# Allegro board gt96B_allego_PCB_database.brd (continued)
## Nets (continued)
GND: BT1.3(N) C1.2(B<0>) C2.2(B<0>) C3.2(B<0>) C4.2(B<0>) C5.2(B<0>) C6.2(B<0>) C7.2(B<0>) C9.2(B<0>) C10.2(B<0>) C11.2(B<0>) C12.2(B<0>) C15.2(B<0>) C18.2(B<0>) C19.2(B<0>) C20.2(B<0>) C21.2(B<0>) C22.2(B<0>) C23.2(B<0>) C24.2(B<0>) C25.2(B<0>) C26.2(B<0>) C27.2(B<0>) C28.2(B<0>) C29.2(B<0>) C30.2(B<0>) C31.2(B<0>) C32.2(B<0>) C33.2(B<0>) C34.2(B<0>) C35.2(B<0>) C36.2(B<0>) C37.2(B<0>) C38.2(B<0>) C39.2(B<0>) C40.2(B<0>) C43.2(B<0>) C44.2(B<0>) C45.2(B<0>) C46.2(B<0>) C47.2(B<0>) C48.2(B<0>) C51.2(B<0>) C52.2(B<0>) C53.2(B<0>) C54.2(B<0>) C55.2(B<0>) C56.2(B<0>) C57.2(B<0>) C58.2(B<0>) C59.2(B<0>) C60.2(B<0>) C61.2(B<0>) C62.2(B<0>) C63.2(B<0>) C65.2(B<0>) C66.2(B<0>) C67.2(B<0>) C68.2(B<0>) C69.2(B<0>) C70.2(B<0>) C71.2(B<0>) C72.2(B<0>) C81.2(B<0>) C82.2(B<0>) C83.2(B<0>) C85.2(B<0>) C86.2(B<0>) C88.2(B<0>) C90.2(B<0>) C91.2(B<0>) C92.2(B<0>) C93.2(B<0>) C94.2(B<0>) C95.2(B<0>) C96.2(B<0>) C97.2(B<0>) C98.2(B<0>) C99.2(B<0>) C100.2(B<0>) C105.2(B<0>) C106.2(B<0>) C118.2(B<0>) C120.2(B<0>) C121.2(B<0>) C122.2(B<0>) C123.2(B<0>) C124.2(B<0>) C125.2(B<0>) C126.2(B<0>) C127.2(B<0>) C128.2(B<0>) C129.2(B<0>) C130.2(B<0>) C131.2(B<0>) C132.2(B<0>) C133.2(B<0>) C134.2(B<0>) C137.2(B<0>) C140.2(B<0>) C143.2(B<0>) C144.2(B<0>) C145.2(B<0>) C146.2(B<0>) C147.2(B<0>) C149.2(B<0>) C151.2(B<0>) C152.2(B<0>) C153.2(B<0>) C158.2(B<0>) C159.2(B<0>) C160.2(B<0>) C161.2(B<0>) C162.2(B<0>) CR1.2(PIN2) CR2.2(PIN2) CR7.2(PIN2) CR8.2 CR9.B1(ANODE1) CR9.B2(ANODE2) CR10.B1(ANODE1) CR10.B2(ANODE2) CR11.2(PIN2) CR12.2(PIN2) CR13.2(PIN2) CR14.2(PIN2) CR19.2(A) CR20.B1(ANODE1) CR20.B2(ANODE2) CR23.2(PIN2) CR24.2(PIN2) CR25.2(A) CR26.2(A) CR28.B1(ANODE1) CR28.B2(ANODE2) CR32.2(PIN2) J2.4 J2.10 J2.19 J2.42 J2.48 J2.54 J2.60 J2.66 J2.72 J2.73 J2.82 J2.86 J2.96 J2.98 J2.100 J3.2 J3.5 J3.8 J3.10 J3.16 J3.17 J3.23 J3.24 J3.29 J3.30 J3.35 J3.36 J3.41 J3.42 J3.48 J3.54 J3.60 J3.61 J3.67 J3.74 J3.80 J3.84 J3.85 J3.90 J3.91 J3.93 J3.96 J3.99 J4.2 J5.6(VSS) J5.9(DET_LEVER/GND) J5.11(SHELL_MOUNT1) J5.12(SHELL_MOUNT2) J5.13(SHELL_MOUNT3) J5.14(SHELL_MOUNT4) J6.4(GND) J6.7(GND_DRAIN) J6.10(MTG1) J6.11(MTG2) J6.12(MTG3) J6.13(MTG4) J7.A1 J7.A12 J7.B1 J7.B12 J7.M1(G1) J7.M2(G2) J7.M3(G3) J7.M4(G4) J7.M5(G5) J7.M6(G6) J7.M7(G7) J7.M8(G8) J8.4(GND) J8.7(GND_DRAIN) J8.10(MTG1) J8.11(MTG2) J8.12(MTG3) J8.13(MTG4) J9.1 J10.2(DATA2G) J10.5(DATA1G) J10.8(DATA0G) J10.11(CLKG) J10.17(DDC/CEC_GND) J10.20(SHELL-1) J10.21(SHELL-2) J10.22(SHELL-3) J10.23(SHELL-4) J12.1 J12.2 J12.39 J12.40 J13.6 J13.12 J13.13 J13.18 J13.19 J13.24 J13.25 J13.30 J13.31 J13.37 J13.40 J13.43 J13.46 J13.49 J13.52 J13.55 J13.58 J15.1 J16.1 J17.3 J17.4 J17.5 J18.1 J19.1 J20.2(SHIELD2) J20.3(SHIELD3) J20.4(SHIELD4) J21.2(SHIELD2) J21.3(SHIELD3) J21.4(SHIELD4) J22.1 J23.1 L3.5 L3.6 L4.5 L4.6 L6.5 L6.6 L7.5 L7.6 L8.5 L8.6 L9.5 L9.6 L10.9 L10.10 L11.9 L11.10 L14.5 L14.6 L15.5 L15.6 L18.9 L18.10 L19.9 L19.10 L20.9 L20.10 L21.C2(GND) L23.2(B) L26.2(B) MT1.1 MT1.2 MT1.3 MT1.4 MT1.5 MT1.6 MT1.7 MT1.8 MT3.1 MT3.2 MT3.3 MT3.4 MT3.5 MT3.6 MT3.7 MT3.8 Q1.2(S) Q2.2(S) Q3.1(Q2E) Q3.4(Q1E) Q4.1(Q2E) Q4.4(Q1E) Q5.4(G) R5.1(A<0>) R14.2(B<0>) R16.2(B<0>) R18.2(B<0>) R20.2(B<0>) R23.2(B<0>) R26.2(B<0>) R27.1(A<0>) R31.2(B<0>) R35.2(B<0>) R36.2(B<0>) R37.2(B<0>) R41.1(A<0>) R42.1(A<0>) R43.1(A<0>) R45.2(B<0>) R51.2(B<0>) R54.2(B<0>) R55.2(B<0>) R56.1(A<0>) R58.2(B<0>) R62.2(B<0>) R64.1(A<0>) R65.1(A<0>) R68.2(B<0>) R77.2(B<0>) R79.2(B<0>) R80.2(B<0>) R82.2(B<0>) R102.2(B<0>) R103.2(B<0>) R104.2(B<0>) R116.2(B<0>) R124.2(B<0>) R132.2(B<0>) R143.2(B<0>) R145.2(B<0>) SW2.1 SW2.2 TP59.1(A) U1.C3(GND_1) U2.65(EP_GND) U3.14(GND) U3.33(EPAD) U4.C2(GND) U5.2(GND1) U5.3(GND2) U5.9(EPAD) U6.2(PD) U6.5(GND_1) U6.11(GND_2) U6.20(GND_3) U6.21(GND_4) U14.4(VSS) U15.5(GND) U15.7(E_PAD) U16.5(GND) U16.7(E_PAD) U17.5(GND) U17.7(E_PAD) U18.7(GND) U18.9(E_PAD) U19.C2(GND) U20.C2(GND) U21.7(GND) U21.9(E_PAD) U22.5(GND) U22.7(E_PAD) U24.C2(GND) U26.5(GND) U26.7(E_PAD) U27.2(GND1) U27.3(GND2) U27.9(EPAD) Y1.2(Y2) Y1.4(Y4)
VBATTERY: J2.92 R33.1(A<0>)
VBUS_USBA_1: C132.1(A<0>) CR9.A1(CATHODE1) CR9.A2(CATHODE2) FB7.2(B) J6.1(VBUS)
VBUS_USBA_2: C133.1(A<0>) CR20.A1(CATHODE1) CR20.A2(CATHODE2) FB8.2(B) J8.1(VBUS)
1P8_ISET: R145.1(A<0>) U24.C1(ISET)
1P8_OUT_OCFLAG_N: TP42.1(A) U24.A1(FLAGB)
5P0V_BOOT: C148.1(A<0>) U21.1(BOOT)
5P0V_COMP: C150.1(A<0>) C151.1(A<0>) U21.6(COMP)
5P0V_EN: R78.2(B<0>) R79.1(A<0>) U21.3(EN)
5P0V_PH: C148.2(B<0>) CR25.1(K) L30.1 U21.8(PH)
5P0V_SENSE: R81.2(B<0>) R82.1(A<0>) U21.5(VSENSE)
5P0V_SS: C149.1(A<0>) U21.4(SS)
+1P1V_SW: L5.1(A) U5.7(SW)
+1P8V_BREAKOUT: C144.1(A<0>) CR2.1(PIN1) J12.35 U24.B1(VOUT)
+SYS_DCIN: C54.1(A<0>) CR26.1(C) F4.2 J12.36 J12.38
+VDC_IN: C51.1(A<0>) C52.1(A<0>) C93.1(A<0>) C94.1(A<0>) C95.1(A<0>) C129.1(A<0>) C145.1(A<0>) C146.1(A<0>) C147.1(A<0>) F1.2 J2.37 R25.1(A<0>) U18.2(VIN) U21.2(VIN)
+VLDO_SDCARD: C120.1(A<0>) U1.B4(VLDO)
+VRTC: C128.1(A<0>) J2.11 R4.1(A<0>)
+VRTC_R: BT1.1(P1) BT1.2(P2) CR13.1(PIN1) R4.2(B<0>)
+VSYS: C39.1(A<0>) C40.1(A<0>) C43.1(A<0>) C44.1(A<0>) C45.1(A<0>) C46.1(A<0>) C47.1(A<0>) C48.1(A<0>) C118.1(A<0>) C121.1(A<0>) C125.1(A<0>) C134.1(A<0>) C137.1(A<0>) J2.2 J2.5 J2.7 J2.12 J2.15 J2.17 J3.1 J3.3 J3.20 J3.22 J3.32 J3.34 R33.2(B<0>) R66.2(B<0>) TP63.1(A)
BLDRW_0_PWM: J3.56 J12.28
BTN_N: J2.84 J12.26
CHRG_INT_N: J2.40 J12.23
CLK_19P2M: J2.71 R39.1(A<0>)
CLK_19P2M_CONN: C83.1(A<0>) J13.15 R39.2(B<0>)
CODEC_MCLK: J2.43 R7.1(A<0>)
CODEC_MCLK_CONN: C7.1(A<0>) J13.17 R7.2(B<0>)
DCIN_EN: R17.2(B<0>) R18.1(A<0>) U3.8(DCIN_EN)
DDI1_CTRL_CLK: J2.68 R11.2(B<0>) U3.31(SCL_SRC)
DDI1_CTRL_DAT: J2.70 R10.2(B<0>) U3.32(SDA_SRC)
DISPLAY_0_RST_N: J3.68 J12.30
DNX_BTN_1P8: R98.2(B<0>) SW3.3 SW3.4
EEPROM_E2: R131.2(B<0>) R132.1(A<0>) U14.3(E2)
EEPROM_VCC: R133.2(B<0>) TP56.1(A) U14.8(VCC)
EEPROM_WC_N: R102.1(A<0>) R134.2(B<0>) U14.7(WC*)
EN_1P1V: C160.1(A<0>) R52.2(B<0>) U5.1(EN)
EN_3P3V: C158.1(A<0>) R34.2(B<0>) U27.1(EN)
EQ: R15.2(B<0>) R16.1(A<0>) U3.13(EQ)
FB_1P1V: R53.2(B<0>) R56.2(B<0>) U5.4(FB)
FB_3P3V: R44.2(B<0>) R45.1(A<0>) U27.4(FB)
FLASH_TORCH: J3.75 J12.25
FULLPWRMGMTZ: R27.2(B<0>) U2.40(FULLPWRMGMT_N/SMBA1/SS_UP)
GANGED: R5.2(B<0>) U2.42(GANGED/SMBA2/HS_UP)
GPIO_22: J2.94 J12.34
GRST_N: C2.1(A<0>) Q1.3(D) U2.50(GRST_N)
HDMI_5V_EN: C159.1(A<0>) R146.2(B<0>) U26.4(EN)
HDMI_5V_I_ADJ: R143.1(A<0>) U26.2(ILIM)
HDMI_5V_OCFLAG_N: R140.2(B<0>) R146.1(A<0>) U26.3(FAULT*)
HDMI_CEXT: C21.1(A<0>) U3.17(CEXT)
HDMI_CLK_C_DN: C73.2(B<0>) U3.10(IN_CKN)
HDMI_CLK_C_DP: C77.2(B<0>) U3.9(IN_CKP)
HDMI_CLK_CONN_DN: J10.12(CLK-) L11.5
HDMI_CLK_CONN_DP: J10.10(CLK+) L11.6
HDMI_CLK_DN: C73.1(A<0>) J2.46
HDMI_CLK_DP: C77.1(A<0>) J2.44
HDMI_DAT0_CONN_DN: J10.9(DATA0-) L11.7
HDMI_DAT0_CONN_DP: J10.7(DATA0+) L11.8
HDMI_DAT1_CONN_DN: J10.6(DATA1-) L10.5
HDMI_DAT1_CONN_DP: J10.4(DATA1+) L10.6
HDMI_DAT2_CONN_DN: J10.3(DATA2-) L10.7
HDMI_DAT2_CONN_DP: J10.1(DATA2+) L10.8
HDMI_OB_CLK_DN: L11.4 U3.18(OUT_CKN)
HDMI_OB_CLK_DP: L11.3 U3.19(OUT_CKP)
HDMI_OB_DAT0_DN: L11.2 U3.21(OUT_D0N)
HDMI_OB_DAT0_DP: L11.1 U3.22(OUT_D0P)
HDMI_OB_DAT1_DN: L10.4 U3.23(OUT_D1N)
HDMI_OB_DAT1_DP: L10.3 U3.24(OUT_D1P)
HDMI_OB_DAT2_DN: L10.2 U3.26(OUT_D2N)
HDMI_OB_DAT2_DP: L10.1 U3.27(OUT_D2P)
HDMI_OB_HPD_INV: CR14.1(PIN1) J10.19(HP_DET) R77.1(A<0>) U3.25(HPD_SNK)
HDMI_OB_SCL: J10.15(SCL) R22.2(B<0>) U3.28(SCL_SNK)
HDMI_OB_SCL_D: CR4.1(C) R22.1(A<0>)
HDMI_OB_SDA: J10.16(SDA) R21.2(B<0>) U3.29(SDA_SNK)
HDMI_OB_SDA_D: CR5.1(C) R21.1(A<0>)
HDMI_PRE: R19.2(B<0>) R20.1(A<0>) U3.15(PRE)
HDMI_REXT: R37.1(A<0>) U3.16(REXT)
HDMI_TX_0_C_DN: C74.2(B<0>) U3.7(IN_D0N)
HDMI_TX_0_C_DP: C78.2(B<0>) U3.6(IN_D0P)
HDMI_TX_0_DN: C74.1(A<0>) J2.62
HDMI_TX_0_DP: C78.1(A<0>) J2.64
HDMI_TX_1_C_DN: C75.2(B<0>) U3.5(IN_D1N)
HDMI_TX_1_C_DP: C79.2(B<0>) U3.4(IN_D1P)
HDMI_TX_1_DN: C75.1(A<0>) J2.58
HDMI_TX_1_DP: C79.1(A<0>) J2.56
HDMI_TX_2_C_DN: C76.2(B<0>) U3.2(IN_D2N)
HDMI_TX_2_C_DP: C80.2(B<0>) U3.1(IN_D2P)
HDMI_TX_2_DN: C76.1(A<0>) J2.50
HDMI_TX_2_DP: C80.1(A<0>) J2.52
HPD_SRC: J2.65 Q2.3(D) R136.2(B<0>)
HPD_SRC_N: Q2.1(G) R9.2(B<0>) R51.1(A<0>) U3.3(HPD_SRC)
HS_PIN60_RFU: J13.60 R8.2(B<0>)
HUB1_USB2_1_DN: U2.2(USB_DM_DN1) U20.A2(IN1)
HUB1_USB2_1_DP: U2.1(USB_DP_DN1) U20.B2(IN2)
HUB1_USB3_1_RX_DN: L3.4 U2.7(USB_SSRXM_DN1)
HUB1_USB3_1_RX_DP: L3.3 U2.6(USB_SSRXP_DN1)
HUB1_USB3_1_TX_DN: C13.2(B<0>) L4.4
HUB1_USB3_1_TX_DN_C: C13.1(A<0>) U2.4(USB_SSTXM_DN1)
HUB1_USB3_1_TX_DP: C14.2(B<0>) L4.3
HUB1_USB3_1_TX_DP_C: C14.1(A<0>) U2.3(USB_SSTXP_DN1)
HUB2_USB2_1_DN: U2.10(USB_DM_DN2) U19.A2(IN1)
HUB2_USB2_1_DP: U2.9(USB_DP_DN2) U19.B2(IN2)
HUB2_USB3_1_RX_DN: L14.4 U2.15(USB_SSRXM_DN2)
HUB2_USB3_1_RX_DP: L14.3 U2.14(USB_SSRXP_DN2)
HUB2_USB3_1_TX_DN: C16.2(B<0>) L15.4
HUB2_USB3_1_TX_DN_C: C16.1(A<0>) U2.12(USB_SSTXM_DN2)
HUB2_USB3_1_TX_DP: C17.2(B<0>) L15.3
HUB3_USB2_1_CONN_DN: J13.53 L21.B1(OUT2)
HUB3_USB2_1_CONN_DP: J13.51 L21.A1(OUT1)
HUB3_USB2_1_DN: L21.B2(IN2) U2.18(USB_DM_DN3)
HUB3_USB2_1_DP: L21.A2(IN1) U2.17(USB_DP_DN3)
HUB3_USB3_1_TX_DP_C: C17.1(A<0>) U2.11(USB_SSTXP_DN2)
HUB4_USB2_1_DN: TP65.1(A) U2.25(USB_DM_DN4)
HUB4_USB2_1_DP: TP64.1(A) U2.24(USB_DP_DN4)
HUB_XI: C3.1(A<0>) R29.1(A<0>) U2.62(XI) Y1.1(Y1)
HUB_XO: C12.1(A<0>) R29.2(B<0>) U2.61(XO) Y1.3(Y3)
HW_RST_N: J12.6 R137.1(A<0>)
I2C_0_SCL: J2.57 R141.1(A<0>)
I2C_0_SCL_EE_R: R141.2(B<0>) TP68.1(A) U14.6(SCL)
I2C_0_SDA: J2.95 R142.2(B<0>)
I2C_0_SDA_EE_R: R142.1(A<0>) TP57.1(A) U14.5(SDA)
I2C_1_SCL: J3.43 J13.32
I2C_1_SDA: J3.45 J13.34
I2C_2_SCL: J3.28 J13.36
I2C_2_SDA: J3.26 J13.38
I2S_1_CLK: J2.39 J12.18
I2S_1_FS: J2.45 J12.16
I2S_1_RXD: J2.47 J12.22
I2S_1_TXD: J2.49 J12.20
INTD_DSI_TE_1: J3.82 J12.29
ISH_GPIO_0: J2.25 R49.1(A<0>)
ISH_GPIO_0_R: Q3.5(Q1B) R49.2(B<0>)
ISH_GPIO_1: J2.27 R50.1(A<0>)
ISH_GPIO_1_R: Q3.2(Q2B) R50.2(B<0>)
ISH_GPIO_2: J2.32 R47.1(A<0>)
ISH_GPIO_2_R: Q4.2(Q2B) R47.2(B<0>)
ISH_GPIO_3: J2.34 R48.1(A<0>)
ISH_GPIO_3_R: Q4.5(Q1B) R48.2(B<0>)
ISH_GPIO_4: J2.29 J12.27
ISH_GPIO_5: J2.38 J12.24
ISH_GPIO_6: J2.31 J12.31
ISH_I2C_0_SCL: J2.16 J12.15
ISH_I2C_0_SDA: J2.18 J12.17
ISH_I2C_1_SCL: J2.21 J12.19
ISH_I2C_1_SDA: J2.23 J12.21
ISH_UART_0_CTS: J3.9 J13.2
ISH_UART_0_RTS: J3.11 J13.4
LED0_A: CR15.2(A) R93.2(B<0>)
LED0_C: CR15.1(C) Q3.3(Q1C)
LED1_A: CR16.2(A) R95.2(B<0>)
LED1_C: CR16.1(C) Q3.6(Q2C)
LED2_A: CR17.2(A) R94.2(B<0>)
LED2_C: CR17.1(C) Q4.6(Q2C)
LED3_A: CR18.2(A) R96.2(B<0>)
LED3_C: CR18.1(C) Q4.3(Q1C)
LS_CFG: R13.2(B<0>) R14.1(A<0>) U3.20(CFG)
LS_PD_N: R12.2(B<0>) U3.12(PD*)
MDSI_A_CLK_CONN_DN: J13.23 L19.5
MDSI_A_CLK_CONN_DP: J13.21 L19.6
MDSI_A_CLK_DN: J3.27 L19.4
MDSI_A_CLK_DP: J3.25 L19.3
MDSI_A_DATA_0_CONN_DN: J13.29 L19.8
MDSI_A_DATA_0_CONN_DP: J13.27 L19.7
MDSI_A_DATA_0_DN: J3.19 L19.1
MDSI_A_DATA_0_DP: J3.21 L19.2
MDSI_A_DATA_1_CONN_DN: J13.35 L18.8
MDSI_A_DATA_1_CONN_DP: J13.33 L18.7
MDSI_A_DATA_1_DN: J3.31 L18.1
MDSI_A_DATA_1_DP: J3.33 L18.2
MDSI_A_DATA_2_CONN_DN: J13.41 L18.6
MDSI_A_DATA_2_CONN_DP: J13.39 L18.5
MDSI_A_DATA_2_DN: J3.37 L18.3
MDSI_A_DATA_2_DP: J3.39 L18.4
MDSI_A_DATA_3_CONN_DN: J13.47 L20.6
MDSI_A_DATA_3_CONN_DP: J13.45 L20.5
MDSI_A_DATA_3_DN: J3.76 L20.3
MDSI_A_DATA_3_DP: J3.78 L20.4
NC_AVS_M_CLK_A1: J3.52
NC_AVS_M_CLK_B1: J3.62
NC_AVS_M_DATA_1: J3.66
NC_CAM_1_CLK: J3.69
NC_CHRG_EN_N: J2.35
NC_DISPLAY_0_BIAS_EN: J3.64
NC_DISPLAY_0_BKLTEN: J3.58
NC_FLASH_TRIGGER: J3.71
NC_ISH_UART_0_RXD: J3.13
NC_ISH_UART_0_TXD: J3.15
NC_PIN92: J3.92
NC_PIN94: J3.94
NC_PIN98: J3.98
NC_PIN100: J3.100
NC_PMIC_SLPCLK_1: J3.7
NC_PWM_0: J2.1
NC_PWM_1: J2.3
NC_SPI_0_FS1: J3.79
NC_SPI_0_FS2: J3.53
NC_SPI_1_FS2: J2.14
NC_TP_PIN_12: J3.12
NC_TP_PIN_14: J3.14
NC_TP_PIN_38: J3.38
NC_TP_PIN_40: J3.40
OTG_EN: J2.69 R61.1(A<0>) TP24.1(A)
OTG_EN_R: R61.2(B<0>) U22.4(EN)
OTG_I_ADJ: R62.1(A<0>) U22.2(ILIM)
OTG_OCFLAG_TP: TP32.1(A) U22.3(FAULT*)
PCIE1_CLK_DN: J3.88 TP7.1(A)
PCIE1_CLK_DP: J3.86 TP6.1(A)
PCIE1_CLKREQ_N: J3.50 TP3.1(A)
PCIE1_PERST_N: J3.70 TP4.1(A)
PCIE1_WAKE_N: J3.72 TP5.1(A)
PMIC_PWRBTN_N: CR24.1(PIN1) CR32.1(PIN1) J2.9 J12.4 R137.2(B<0>) SW2.3 SW2.4
PMIC_PWRGOOD: J2.33 TP50.1(A)
PMIC_RESET_N: J2.13 TP49.1(A)
PWM_2: J2.22 J12.32
PWM_3: J2.24 J12.33
PWRCTL_POL: R65.2(B<0>) U2.41(PWRCTL_POL)
PWRGOOD_1P1V: R57.2(B<0>) U5.6(PG)
PWRGOOD_3P3V: R46.2(B<0>) U27.6(PG)
R1_SENSE_N: J1.2 R1.5
R1_SENSE_P: J1.1 R1.2
RF_ANT_WIFI_A: AT1.1(A) L24.2(B) R116.1(A<0>)
RF_ANT_WIFI_B_BT: AT2.1(A) L27.2(B) R124.1(A<0>)
RF_CONN_WIFI_A: J20.1(CENTER) R115.1(A<0>)
RF_CONN_WIFI_B_BT: J21.1(CENTER) R120.1(A<0>)
RF_MATCH_WIFI_A: L22.1(A) R115.2(B<0>)
RF_MATCH_WIFI_A_L: C85.1(A<0>) L22.2(B) L23.1(A) L24.1(A)
RF_MATCH_WIFI_B_BT: L25.1(A) R120.2(B<0>)
RF_MATCH_WIFI_B_BT_L: C86.1(A<0>) L25.2(B) L26.1(A) L27.1(A)
RFU_FAN: J17.2 TP35.1(A)
SDCARD_CD_N: J2.79 R100.1(A<0>)
SDCARD_CD_N_CONN: J5.10(DET_SWITCH) R100.2(B<0>) U1.D3(CD)
SDCARD_CLK: J2.75 U1.C1(CLK_IN)
SDCARD_CLK_CONN: C1.1(A<0>) J5.5(CLK) R32.2(B<0>)
SDCARD_CLK_CONN_R: R32.1(A<0>) U1.C5(CLK_SD)
SDCARD_CMD: J2.89 U1.D2(CMD_H)
SDCARD_CMD_CONN: J5.3(CMD) U1.D4(CMD_SD)
SDCARD_D0: J2.81 U1.D1(DATA0_H)
SDCARD_D0_CONN: J5.7(DAT0) U1.D5(DATA0_SD)
SDCARD_D1: J2.83 U1.E1(DATA1_H)
SDCARD_D1_CONN: J5.8(DAT1) U1.E5(DATA1_SD)
SDCARD_D2: J2.85 U1.A1(DATA2_H)
SDCARD_D2_CONN: J5.1(DAT2) U1.A5(DATA2_SD)
SDCARD_D3: J2.87 U1.B1(DATA3_H)
SDCARD_D3_CONN: J5.2(CD/DAT3) U1.B5(DATA3_SD)
SDCARD_LVL_CLK_FB: J2.77 U1.E2(CLK_FB)
SDCARD_LVL_CMD_DIR: J2.90 U1.A2(DIR_CMD)
SDCARD_LVL_DAT_DIR: J2.67 U1.A3(DIR_0) U1.E3(DIR_1_3)
SDCARD_LVL_SEL: J2.88 U1.B2(SEL)
SDCARD_PWR_DOWN_N: J2.91 R36.1(A<0>) U1.C2(ENABLE)
SPI_0_CLK: J3.59 J13.9
SPI_0_FS0: J3.77 J13.7
SPI_0_MISO: J3.49 J13.11
SPI_0_MOSI: J3.57 J13.1
SPI_1_CLK: J2.53 J12.8
SPI_1_FS0: J2.55 J12.12
SPI_1_MISO: J2.63 J12.10
SPI_1_MOSI: J2.51 J12.14
TP_HDMI_CEC: J10.13(CEC) TP1.1(A)
TP_USB_TYPC_SBU1_CONN: J7.A8 TP17.1(A)
TP_USB_TYPC_SBU2_CONN: J7.B8 TP18.1(A)
UART_0_CTS: J3.47 J12.3
UART_0_RTS: J3.55 J12.9
UART_0_RXD: J3.51 J12.7
UART_0_TXD: J2.93 J12.5
UART_1_RXD: J2.26 TP8.1(A)
UART_1_TXD: J2.28 TP9.1(A)
UART_2_CTS: J2.74 J9.6
UART_2_RTS: J2.76 J9.2
UART_2_RXD: J2.80 J9.4 J12.13
UART_2_TXD: CR23.1(PIN1) J2.78 J9.5 J12.11 SW3.1 SW3.2
UNNAMED_11_RES_I102_B: R64.2(B<0>) U2.60(NC_1)
UNNAMED_20_FPF2195_I476_ON: R138.2(B<0>) U24.A2(ON)
UNNAMED_56_CAP_I271_B: C89.2(B<0>) R23.1(A<0>)
UNNAMED_56_CAP_I302_B: C150.2(B<0>) R80.1(A<0>)
USB2_0_DN: J2.8 U4.B1(OUT2)
USB2_0_DP: J2.6 U4.A1(OUT1)
USB2_1_DN: J3.63 U2.54(USB_DM_UP)
USB2_1_DP: J3.65 U2.53(USB_DP_UP)
USB2_ID_PMIC: J2.20 TP14.1(A)
USB3_0_MUX1_RX_DN: L7.3 U6.16(RX1-)
USB3_0_MUX1_RX_DP: L7.4 U6.17(RX1+)
USB3_0_MUX1_TX_DN: L6.3 U6.18(TX1-)
USB3_0_MUX1_TX_DP: L6.4 U6.19(TX1+)
USB3_0_MUX2_RX_DN: L9.3 U6.12(RX2-)
USB3_0_MUX2_RX_DP: L9.4 U6.13(RX2+)
USB3_0_MUX2_TX_DN: L8.3 U6.14(TX2-)
USB3_0_MUX2_TX_DP: L8.4 U6.15(TX2+)
USB3_0_RX_DN: J3.44 U6.8(RX-)
USB3_0_RX_DP: J3.46 U6.7(RX+)
USB3_0_TX_DN: J3.6 U6.4(TX-)
USB3_0_TX_DP: J3.4 U6.3(TX+)
USB3_1_RX_DN: C155.1(A<0>) J3.97
USB3_1_RX_DN_C: C155.2(B<0>) U2.56(USB_SSTXM_UP)
USB3_1_RX_DP: C154.1(A<0>) J3.95
USB3_1_RX_DP_C: C154.2(B<0>) U2.55(USB_SSTXP_UP)
USB3_1_TX_DN: J3.89 U2.59(USB_SSRXM_UP)
USB3_1_TX_DP: J3.87 U2.58(USB_SSRXP_UP)
USB_HUB_AUTOEN_N: R42.2(B<0>) U2.45(AUTOEN_N/HS_SUSBEND)
USB_HUB_OVERCUR1_N: R2.2(B<0>) U2.46(OVERCUR1_N) U15.3(FAULT*)
USB_HUB_OVERCUR2_N: R3.2(B<0>) U2.47(OVERCUR2_N) U16.3(FAULT*)
USB_HUB_OVERCUR3_N: TP11.1(A) U2.44(OVERCUR3_N)
USB_HUB_OVERCUR4_N: TP12.1(A) U2.43(OVERCUR4_N)
USB_HUB_PWRCTL1: R38.2(B<0>) R104.1(A<0>) U2.36(PWRCTL1/BATEN1) U15.4(EN)
USB_HUB_PWRCTL2: R28.2(B<0>) R103.1(A<0>) U2.35(PWRCTL2/BATEN2) U16.4(EN)
USB_HUB_PWRCTL3: TP13.1(A) U2.33(PWRCTL3/BATEN3)
USB_HUB_PWRCTL4: TP15.1(A) U2.32(PWRCTL4/BATEN4)
USB_HUB_RST: J3.73 Q1.1(G)
USB_HUB_SCL: TP16.1(A) U2.38(SCL/SMBCLK)
USB_HUB_SDA: TP19.1(A) U2.37(SDA/SMBDAT)
USB_HUB_SMBUS_N: R63.2(B<0>) TP20.1(A) U2.39(SMBUS_N/SS_SUSPEND)
USB_HUB_TEST: R41.2(B<0>) U2.49(TEST)
USB_R1: R43.2(B<0>) U2.64(USB_R1)
USB_TYPC_CC1: C20.1(A<0>) FB4.2(B) J2.59
USB_TYPC_CC2: C19.1(A<0>) FB5.2(B) J2.61
USB_TYPC_CONN_CC1: CR12.1(PIN1) FB4.1(A) J7.A5
USB_TYPC_CONN_CC2: CR11.1(PIN1) FB5.1(A) J7.B5
USB_VBUS: R30.2(B<0>) R35.1(A<0>) U2.48(USB_VBUS)
USBA_1_USB2_1_DN: J6.2(D-) U20.A1(OUT1)
USBA_1_USB2_1_DP: J6.3(D+) U20.B1(OUT2)
USBA_1_USB3_1_RX_DN: J6.5(STDA_SSRX-) L3.1
USBA_1_USB3_1_RX_DP: J6.6(STDA_SSRX+) L3.2
USBA_1_USB3_1_TX_DN: J6.8(STDA_SSTX-) L4.1
USBA_1_USB3_1_TX_DP: J6.9(STDA_SSTX+) L4.2
USBA_2_USB2_1_DN: J8.2(D-) U19.A1(OUT1)
USBA_2_USB2_1_DP: J8.3(D+) U19.B1(OUT2)
USBA_2_USB3_1_RX_DN: J8.5(STDA_SSRX-) L14.1
USBA_2_USB3_1_RX_DP: J8.6(STDA_SSRX+) L14.2
USBA_2_USB3_1_TX_DN: J8.8(STDA_SSTX-) L15.1
USBA_2_USB3_1_TX_DP: J8.9(STDA_SSTX+) L15.2
USBA_CONN1_I_ADJ: R54.1(A<0>) U15.2(ILIM)
USBA_CONN2_I_ADJ: R58.1(A<0>) U16.2(ILIM)
USBC_SEL: J3.18 R68.1(A<0>) U6.9(SEL)
USBC_USB2_0_DN: J7.A7 J7.B7 U4.B2(IN2)
USBC_USB2_0_DP: J7.A6 J7.B6 U4.A2(IN1)
USBC_USB3_0_MUX1_RX_DN: J7.B10 L7.2
USBC_USB3_0_MUX1_RX_DP: J7.B11 L7.1
USBC_USB3_0_MUX1_TX_DN: J7.A3 L6.2
USBC_USB3_0_MUX1_TX_DP: J7.A2 L6.1
USBC_USB3_0_MUX2_RX_DN: J7.A10 L9.2
USBC_USB3_0_MUX2_RX_DP: J7.A11 L9.1
USBC_USB3_0_MUX2_TX_DN: J7.B3 L8.2
USBC_USB3_0_MUX2_TX_DP: J7.B2 L8.1
VCONN_DCDC_EN: J2.97 TP25.1(A) U17.4(EN)
VCONN_I_ADJ: R55.1(A<0>) U17.2(ILIM)
VCONN_OCFLAG_TP: TP33.1(A) U17.3(FAULT*)
VDC_IN_CONN: J4.1 R1.1 R1.3
VDC_IN_FET: F1.1 Q5.1(S1) Q5.2(S2) Q5.3(S3)
VDC_IN_R: CR8.1 F4.1 Q5.5(D1) Q5.6(D2) Q5.7(D3) Q5.8(D4) Q5.9(D5) R1.4 R1.6
VSYS_REG_BOOT: C87.1(A<0>) U18.1(BOOT)
VSYS_REG_COMP: C89.1(A<0>) C90.1(A<0>) U18.6(COMP)
VSYS_REG_EN: R25.2(B<0>) R26.1(A<0>) U18.3(EN)
VSYS_REG_OUT: C91.1(A<0>) C92.1(A<0>) C99.1(A<0>) L29.2 R24.1(A<0>) R66.1(A<0>) TP62.1(A)
VSYS_REG_PH: C87.2(B<0>) CR19.1(K) L29.1 U18.8(PH)
VSYS_REG_SENSE: R24.2(B<0>) R31.1(A<0>) U18.5(VSENSE)
VSYS_REG_SS: C88.1(A<0>) U18.4(SS)

Pads without a net: J3 81 83; J4 3; J9 3; J10 14; J13 3 5 8 10 14 16 20 22 26 28 42 44 48 50 54 56 57 59; L20 1 2 7 8; LB1 1; LB* 1; MT2 1 2 3 4 5 6 7 8; MT4 1 2 3 4 5 6 7 8; NOREF#56 1; NOREF#58 1; NOREF#61 1; U1 E4; U2 19 20 22 23 26 27 29 30; U14 1 2

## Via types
v1: diameter 0.5, hole 0.25, TOP to BOTTOM, 1520 vias
v2: diameter 0.635, hole 0.318, TOP to BOTTOM, 38 vias
v3: diameter 0.635, hole 0.25, TOP to BOTTOM, 33 vias
v4: diameter 0.22, hole 0.1, L5 to BOTTOM, 23 vias

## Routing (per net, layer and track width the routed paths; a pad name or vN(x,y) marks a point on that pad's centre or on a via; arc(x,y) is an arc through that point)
+5VP0V_HDMI_CONN:
  vias: v1(20.52,8.18) v1(21.24,7.86)
+5VP0V_HDMI_OUT_FILT:
  vias: v2(21.28,5.57)
+V1P1V: length 3.1
  TOP w0.2: R53.1 59.68,35.23 60.28,35.23 60.32,35.19 61.73,35.19 62.23,35.69 C18.1
  vias: v1(62.67,36.8)
+V1P1V_USB_HUB: length 16.9
  TOP w0.2: U2.21 C56.1 ; v1(59.95,32.08) U2.57 59.95,33.92 C25.1 ; v1(56.45,28.98) U2.8 C57.1 ; v1(56.45,26.48) U2.13 C61.1 ; U2.31 C58.1 ; C33.1 U2.28 ; C38.1 U2.5 v1(56.45,30.48)
  TOP w0.25: v1(56.45,26.48) 56.95,25.98 56.95,25.64 57.25,25.34 58.05,25.34 58.48,24.91 ; 58.48,24.91 58.45,24.88 U2.21 ; 58.48,24.91 61.96,24.91 ; 61.96,24.91 61.95,24.89 U2.28 ; 61.96,24.91 61.97,24.89 63.2,24.89 63.45,24.64 U2.31
  vias: v1(63.05,32.48) v1(63.05,33.66) v1(63.4,34.02) v1(64.21,34.02)
+V1P8V: length 113.2
  TOP w0.2: v1(45.19,20.65) R8.1
  TOP w0.25: R138.1 43.64,43.59 U24.B2 ; R131.1 36,40.26 36,36.85 37.91,34.94 v1(37.91,30.67) C105.1 R133.1 R134.1
  TOP w0.3: v3(27.85,20.48) 27.85,22.86 29.06,24.07 v1(29.06,24.71) 29.26,24.91 29.68,24.91 29.68,24.2 C124.1
  TOP w0.35: R138.1 43.64,42.78 C143.1 43.64,42.78 R98.1 43.64,40.96
  TOP w0.5: v1(42.34,24.25) v1(42.69,24.6) 42.73,24.6 43.08,24.96 43.08,25.66 40.8,27.95 40.8,28.48 40.4,28.88 v1(40.4,30.67) 40.4,37.72 43.64,40.96
  L5 w0.25: v3(27.85,20.48) 26.64,20.48 26.08,21.04 25.69,21.04 25.13,20.48 19.02,20.48 14.53,24.98 8.4,24.98 6.82,23.39 v1(6.82,22.44)
  BOTTOM w0.2: FB1.1 v1(6.82,22.44) ; v1(45.19,20.65) 45.19,22.16 44.97,22.38 44.97,22.99 43.36,24.6 v1(42.69,24.6) ; 19.71,14.43 19.24,13.95 19.24,12.36 19.63,11.97 20.81,11.97 21.53,12.69 C140.1 C5.1 23.08,12.7 U3.30
  BOTTOM w0.3: 19.71,14.43 19.86,14.58 20.57,14.58 21.79,15.8 23.52,15.8 24.01,16.29 24.91,16.29 25.64,17.02 25.64,18.21 25.94,18.5 R9.1 26.21,18.84 v3(27.85,20.48) 28.15,20.48 29.32,19.31 R136.1 ; v1(37.91,30.67) v1(40.4,30.67)
  BOTTOM w0.5: v1(29.06,24.71) 29.13,24.64 39.36,24.64 39.75,24.25 v1(42.34,24.25) v1(42.69,24.6)
+V1P8V_MICROSD: length 8.3
  TOP w0.25: v1(7.52,17.28) 7.52,17.44 7.81,17.73 C6.1
  L5 w0.2: v4(8.45,17.43) 8.44,17.42 7.68,17.42 7.54,17.28 v1(7.52,17.28) 7.5,17.28 7.36,17.42 6.98,17.42 6.44,17.96
  L5 w0.25: 6.44,17.96 6.44,18.93 5.84,19.53 5.84,20.04 5.59,20.29 5.59,20.68 5.84,20.93 v1(5.84,21.47)
  BOTTOM w0.25: FB1.2 6.18,21.13 v1(5.84,21.47)
+V3P3V: length 44.1
  TOP w0.35: v1(18.29,16.69) 18.29,18.96 R73.1
  L5 w0.4: v1(33.02,15.42) 33.16,15.28 33.16,14.31 32.64,13.79 29.67,13.79 29.2,13.32 24.98,13.32 24.09,14.21 22.09,14.21 19.61,16.69 v1(18.29,16.69)
  L5 w0.5: v1(53.06,35.51) v1(53.56,35.51) v1(54.24,35.51)
  BOTTOM w0.2: R13.1 R19.1 R15.1 R12.1 32.95,14.36 32.9,14.41 32.9,15.3 v1(33.02,15.42) R17.1 ; 29.43,14.06 29.2,14.06
  BOTTOM w0.25: 29.43,14.06 29.49,14.12 30.63,14.12 31.22,14.72 31.22,15.39 C4.1 31.23,15.55 31.23,16.21 C34.1 31.51,16.28 32.37,15.42 v1(33.02,15.42)
  BOTTOM w0.35: v1(18.29,16.69) 18.19,16.59 18.06,16.59 17.4,15.92 17.4,15.51 16.58,14.69 16.48,14.69 16.04,14.25 16.04,14.18 15.73,13.87 15.65,13.87 14.41,12.62 13.48,12.62 13.45,12.6 11.84,12.6 11.75,12.5 C27.1 8.9,12.61 FB2.1
+V3P3V_MICROSD: length 25.3
  TOP w0.25: v1(7.46,2.45) 7.46,1.77 J5.4
  L5 w0.2: v3(7.14,16.16) 7.5,16.52 8.18,16.52 8.26,16.61 8.47,16.61 8.85,16.99 v4(8.85,17.03)
  L5 w0.5: v3(7.14,16.16) 7.14,15.34 6.79,14.99 4.97,14.99 4.11,14.13 4.11,6.16 7.06,3.21 7.06,2.85 v1(7.46,2.45)
  BOTTOM w0.2: v1(7.46,2.45) 7.65,2.45 CR7.1 ; v3(7.14,16.16) 7.16,16.16 7.36,16.36 7.36,16.4 7.99,17.03 U1.A4
  BOTTOM w0.35: v3(7.14,16.16) 7.14,15.94 7.12,15.92 7.12,15.43 C28.1 7.14,14.88 8.16,13.86 FB2.2
+V3P3V_SW: length 0.8
  TOP w0.5: 52.66,38.32 52.66,39.02 v2(52.72,39.07)
+V3P3V_USB_HUB: length 29.2
  TOP w0.2: C26.1 55.86,24.98 U2.16 v1(56.45,24.98) ; U2.63 v1(56.95,32.48) ; C37.1 62.45,33.63 U2.52 v1(62.45,32.48) ; U2.34 65.27,25.48 C55.1 65.48,25.47 65.98,24.98 v1(66.02,24.98) 66.02,24.7 66.36,24.36 67.38,24.36 67.64,24.62 67.64,25.14 R28.1 R38.1 67.3,26.43 67.55,26.68 R63.1 68.16,27.96 68.16,30.92 R2.1 R3.1
  L5 w0.5: v1(62.45,32.48) 62.45,33.92 63.15,34.62 64.46,34.62 65.54,33.54 65.54,29.84 66.02,29.36 v1(66.02,24.98)
  vias: v1(56.55,33.66) v1(57.05,33.66)
+V5P0V: length 15.8
  TOP w0.2: 47.44,37.96 47.45,37.97 R34.1 ; 63.67,15.06 v1(63.67,15.06)
  TOP w0.3: U15.6 71.87,26.85 C29.1
  TOP w0.35: 68.75,32.48 68.75,32.48 C9.1 67.36,32.48 67.36,32.48 R30.1
  BOTTOM w0.2: R140.1 27.5,1.97
  BOTTOM w0.35: 65.68,8.46 65.67,8.45 R94.1 ; R93.1 R95.1 R94.1 ; R94.1 R96.1
  vias: v1(62.16,15.95) v1(62.39,16.39) v1(62.42,15.5) v1(62.66,15.94) v1(62.92,15.51) v1(62.98,14.84) v1(63.42,15.5) v1(63.68,15.93) v1(63.92,16.37) v1(63.92,15.49) v1(64.18,15.92) v1(64.17,15.05) v1(64.42,16.36) v1(64.43,15.49) v1(64.41,14.61) v1(64.68,15.92) v1(64.68,15.05)
+V5P0V_BREAKOUT:
  vias: v2(45.59,46.01)
+V5P0V_USBA_1: length 6.3
  TOP w0.2: C161.1 72.58,21.82 v1(73.39,21.01)
  TOP w0.35: C161.1 71.87,21.82 C31.1 71.87,22.85 U15.1
  TOP w0.5: C30.1 71.87,19.86 C161.1
+V5P0V_USBA_2: length 0.5
  TOP w0.1: C131.1 v1(51.24,18.25)
+V5P0V_VCONN: length 22.4
  L3 w0.4: v1(46.26,28.72) 46.16,28.72 46.16,28.71 v1(45.52,28.71) v1(45.02,28.71) 44.73,28.42 44.73,27.28 43.86,26.41 43.86,23.95 43.25,23.34 39.02,23.34 38.41,23.96 32.33,23.96 30.93,22.56 30.93,22.52 v1(30.91,22.51)
  BOTTOM w0.2: v1(30.91,22.51) 30.91,22.54 30.88,22.57 J2.41
  BOTTOM w0.3: v1(30.91,22.51) 30.93,22.49 30.93,21.75 C126.1
+VBUS: length 0.6
  BOTTOM w0.35: v1(43.32,22.46) C127.1
  vias: v1(44.02,22.46)
+VBUS_USBC: length 3.9
  TOP w0.3: J7.A4 40.4,10.09 J7.B9 ; J7.A9 42.85,8.98 J7.B4
  BOTTOM w0.2: F2.2 44.66,11.84 44.95,12.13 v1(44.95,12.28)
+VBUS_USBC_F: length 3.1
  BOTTOM w0.2: F2.1 44.5,12.6 44.78,12.89 46.5,12.89 v1(46.72,12.67)
+VDD1: length 3
  TOP w0.1: FB11.1 29.68,25.72
  TOP w0.2: v1(29.67,27.48) 29.68,27.48 C123.1 29.68,26.38 29.68,25.72
  BOTTOM w0.2: v1(29.67,27.48) 29.68,27.47 J2.36
+VDD3: length 73.4
  TOP w0.35: C122.1 v1(28.48,26.99)
  L5 w0.2: v1(73.63,17.7) 71.82,19.51 69.18,19.51 68.98,19.71 68.98,28.78 66.96,30.8 66.96,32.6 67.32,32.96 67.32,36.1 65.94,37.48 62.94,37.48 62.76,37.66 58.72,37.66 58.54,37.48 52.05,37.48 50.54,35.97 50.54,35.47 48.34,33.27 47.13,33.27 45.6,31.74 45.6,31.12 45.34,30.86 45.07,30.86 44.37,30.16 43.89,30.16 42.05,28.32 42.05,26.89 41.62,26.46 37.67,26.46 36.91,25.7 28.68,25.7 28.48,25.9 v1(28.48,26.99)
  BOTTOM w0.2: J2.30 v1(28.48,26.99)
  BOTTOM w0.35: R78.1 72.76,19.1 73.35,18.51 73.35,18.03 73.63,17.75 v1(73.63,17.7)
+VDD_USBC_MUX: length 18.3
  TOP w0.2: C67.1 17,17.26 U6.1 ; C65.1 11.34,17.26 U6.10
  TOP w0.25: 13.81,20.09 13.79,20.06 C66.1 13.85,19.13 13.85,18.89 13.92,18.83 U6.6
  TOP w0.35: C65.1 11.16,17.26 11.14,17.25 11.01,17.25 10.91,17.14 10.91,17.06 v1(10.79,16.94) ; 13.81,20.09 14.22,20.5 15.99,20.5 R73.2 17.53,18.64 17.84,18.33 17.84,17.47 v1(17.64,17.26) C67.1
  L5 w0.35: 14.36,17.09 11.05,17.09 10.9,16.94 v1(10.79,16.94)
  L5 w0.4: 14.36,17.09 17.46,17.09 v1(17.64,17.26)
GND: length 1020.4
  TOP w0.2: 56.95,35.37 C24.2 56.49,34.97 ; 56.53,15.34 U19.C2 56.2,15.01 ; R5.1 67.02,29.79 67.16,29.65 R65.1 ; J7.M1 37.7,8.33 ; J7.M1 36.3,8.33 ; J7.M1 37,9.48 ; 61.91,34.47 C37.2 ; J10.21 17.15,5.12 ; J10.21 17.15,2.22 ; J10.21 17.95,3.67 ; J10.21 16.35,3.67 ; 63.47,52.64 SW2.2 ; SW2.2 65.32,51.94 ; SW2.2 65.32,53.33 ; 63,2.5 J8.13 ; J8.13 62.05,3.88 ; J8.13 63,5.26 ; 19.46,10.36 R77.2 ; R77.2 19.46,11.27 ; R77.2 19.06,10.81 ; 62.25,45.92 CR8.2 ; CR8.2 62.25,46.84 ; CR8.2 61.54,46.38 ; CR8.2 62.96,46.38 ; J10.22 33.65,3.67 ; J10.22 32.05,3.67 ; J10.22 32.85,5.12 ; J10.22 32.85,2.22 ; 11.34,16.1 C65.2 ; U6.2 15.92,18.54 ; U6.2 15.92,17.66 ; U6.2 16.25,18.1 ; J6.11 83.3,12.38 ; J6.11 82.4,13.82 ; J6.11 82.4,10.93 ; J6.11 81.5,12.38 ; 5.04,0.8 J5.6 5.04,2.31 v1(5.19,2.46) ; 47.05,31.16 U17.5 47.05,32.06 ; CR23.2 57.34,53.31 ; CR23.2 56.99,53.63 ; CR23.2 56.62,53.31 56.49,53.44 v1(56.49,53.5) ; 60.39,39.47 C160.2 ; C160.2 60.39,40.38 ; C160.2 60.79,39.92 ; 36.35,18.85 J13.40 36.35,16.45 ; v1(66.86,7.37) 66.77,7.28 Q3.1 66.77,5.8 ; v1(59.2,34.83) C25.2 ; v1(65.34,24.16) 65.28,24.22 C55.2 ; 30.44,24.2 30.44,24.66 ; 30.44,24.2 30.44,23.75 ; 30.44,24.2 30.84,24.2 ; J6.13 83.35,3.88 ; J6.13 81.45,3.88 ; J6.13 82.4,2.5 ; J6.13 82.4,5.26 ; 22.75,18.85 J13.6 22.75,16.45 ; 1.13,2.05 J5.14 1.76,0.45 ; 46.29,27.23 R55.2 ; R55.2 45.89,27.69 ; R55.2 46.29,28.14 ; 29.95,16.45 J13.24 29.95,18.85 ; 37.78,11.13 J7.M5 ; J7.M5 38.23,11.48 ; J7.M5 38.23,10.78 ; J7.M4 46.9,5.13 ; J7.M4 45.5,5.13 ; J7.M4 46.2,3.87 ; J7.M4 46.2,6.39 ; 38.41,10.36 38.56,10.26 38.68,10.14 J7.A1 v1(38.85,11.06) ; 25.95,12.05 J13.13 25.95,14.45 ; v1(32.06,19.07) 32.35,18.78 J13.30 32.35,16.45 ; C133.2 52.55,16.52 ; C133.2 52.94,16.07 ; C133.2 52.55,15.62 ; v1(0.98,12.81) J5.12 1.68,14.68 ; 42.47,45.65 C144.2 ; C144.2 42.87,46.1 ; C144.2 42.87,45.2 ; 33.31,40.43 R132.2 33.71,40.88 ; 61.49,39.47 C71.2 ; C71.2 61.09,39.92 ; C71.2 61.49,40.38 ; 59.2,46.8 CR24.2 59.2,47.5 ; C98.2 50.62,30.38 ; C98.2 49.72,30.38 ; C98.2 50.17,30.77 ; 55.86,22.59 C26.2 ; C26.2 56.31,22.99 ; C26.2 55.41,22.99 ; CR13.2 12.66,42.09 ; CR13.2 12.31,42.42 ; CR13.2 11.96,42.09 ; 42.6,44.11 R145.2 42.15,43.71 ; J10.8 26.25,10.62 ; 71.11,23.3 C31.2 71.11,22.39 ; C29.2 73.07,26.76 72.82,26.51 72.82,26.43 72.77,26.37 72.68,26.37 v1(72.52,26.21) U15.5 72.52,25.16 ; C29.2 73.62,26.85 ; C29.2 73.07,27.43 ; 17,16.1 C67.2 17.45,16.5 ; 74.53,22.11 R54.2 ; R54.2 74.53,23.02 ; R54.2 74.93,22.57 ; 16.26,16.43 U6.20 15.82,16.76 ; 54.06,28.98 C57.2 54.46,28.52 ; L4.6 v1(72.09,15.16) ; v1(72.09,15.16) 71.89,14.96 CR9.B1 ; v1(72.09,15.16) 72.09,15.4 71.87,15.62 71.63,15.37 CR9.B2 CR9.B1 ; 34.88,30.27 R102.2 ; 42.47,42.78 C143.2 ; C143.2 42.87,42.33 ; C143.2 42.87,43.23 ; v1(35.27,7.69) L7.5 ; 32.25,7.12 J10.23 ; J10.23 33.05,8.57 ; J10.23 31.45,8.57 ; J10.23 32.25,10.02 ; 42.75,14.45 J13.55 42.75,12.05 ; 53,33.07 R43.1 53.55,33.65 ; 12.08,16.43 U6.11 12.52,16.76 ; v1(35.27,5.87) L7.6 ; 41.72,30.72 C59.2 41.14,31.27 ; Q3.4 v1(68.07,9.15) ; 60.58,38.61 U5.2 59.8,38.61 ; 56.14,36.55 C3.2 v1(55.59,37.01) ; J8.4 60.1,12.37 ; J8.4 60.85,11.63 ; J8.4 60.1,10.88 ; J8.4 59.35,11.63 ; 76,13.87 J6.7 76.75,13.13 ; 60.83,36.35 C18.2 v1(60.04,35.77) ; C56.2 58.91,22.99 ; C56.2 58.45,22.59 ; C56.2 57.99,22.99 ; C66.2 14.95,19.2 ; C66.2 14.55,19.66 ; C66.2 14.46,19.11 14.46,18.9 14.42,18.86 U6.5 14.42,17.66 ; J7.B12 39.33,8.93 ; 73.93,27.17 C52.2 ; C52.2 74.39,27.57 ; C52.2 73.47,27.57 ; 67.53,33.75 67.79,33.49 67.79,33.24 ; 30.44,25.93 30.44,26.38 ; CR20.B2 52.52,15.36 ; 49.85,39.5 C158.2 49.4,39.9 ; 46.2,7.18 J7.M2 ; J7.M2 46.9,8.33 ; J7.M2 45.5,8.33 ; 52.95,18.25 C131.2 52.55,17.8 ; C30.2 76.2,19.35 ; C30.2 75.04,20.82 ; C30.2 75.04,17.88 ; C30.2 73.89,19.35 ; 75.67,15.01 U20.C2 76,15.34 ; 61.95,22.59 C33.2 ; C33.2 62.41,22.99 ; C33.2 61.49,22.99 ; U14.4 33.32,38.77 ; U14.4 32.28,38.77 ; U14.4 32.8,37.43 ; 46.89,45.99 CR1.2 ; CR1.2 47.21,46.34 ; CR1.2 46.89,46.69 ; 66.34,33.95 R41.1 65.94,33.49 ; CR14.2 21.2,11.16 ; 56.6,13.87 J8.7 57.35,13.13 ; v1(71.24,36.63) 71.01,36.4 70.98,36.32 70.98,36.2 ; 27.55,16.45 J13.18 27.55,18.85 ; v1(12.98,41.5) 12.87,41.39 ; 37.95,12.05 J13.43 37.95,14.45 ; J5.9 12.98,14.02 ; J5.9 12.33,13.35 ; J5.9 11.68,14.02 ; v1(11.64,15.91) 11.67,15.91 11.67,15.94 ; J7.A12 v1(44.35,10.94) 44.54,11.13 J7.M8 44.98,10.78 ; 28.35,12.05 J13.19 ; L9.6 v1(48.95,10) ; J7.M7 42.85,11.48 ; 52.84,33.02 52.38,33.02 52.38,33.42 ; 64.36,5.8 Q4.4 ; Q4.4 v1(64.36,7.37) ; Q4.4 63.97,6.51 ; 70.47,21.24 C161.2 ; v1(13.5,1.56) J5.13 ; J5.13 15.19,1.56 ; J5.13 14.42,2.68 ; J5.13 14.42,0.45 ; 65.28,33.24 65.73,33.24 ; 42.81,44.37 U24.C2 43.14,44.04 ; v1(71.54,40.56) 71.58,40.56 ; 30.75,14.45 J13.25 30.75,12.05 ; J8.11 63,13.82 ; J8.11 63,10.93 ; J8.11 63.9,12.38 ; J8.11 62.1,12.38 ; 47.13,45.91 C53.2 47.53,45.46 ; 60.81,36.8 C72.2 61.21,37.26 ; 69.6,10.93 J6.10 ; J6.10 68.7,12.38 ; J6.10 69.6,13.82 ; C128.2 25.65,23.66 ; C128.2 25.65,22.75 ; C128.2 26.05,23.21 ; CR9.B1 71.63,14.64 ; 79.5,10.88 J6.4 ; J6.4 79.5,12.37 ; J6.4 78.75,11.63 ; J6.4 80.25,11.63 ; 14.09,12.81 J5.11 ; J5.11 15.19,12.81 ; J5.11 14.64,10.95 ; Q4.1 v1(65.66,9.15) ; 50.48,38.23 U27.2 49.7,38.23 ; 11.61,18.39 R68.2 ; R68.2 11.61,19.3 ; R68.2 11.21,18.84 ; C23.2 63.23,34.77 62.78,34.77 v1(62.53,35.02) ; 60.93,40.35 C70.2 ; 49.14,31.65 C162.2 49.72,31.01 ; 51.73,31.16 U16.5 v1(51.73,32.21) 51.52,32.42 C96.2 51.52,33.54 ; J6.12 70.55,3.88 ; J6.12 68.65,3.88 ; J6.12 69.6,2.5 ; J6.12 69.6,5.26 ; C105.2 37.31,31.83 ; J10.2 29.25,10.62 ; v1(65.88,36.19) 65.83,36.15 Q1.2 ; 59.02,53.33 SW2.1 59.02,51.94 ; C130.2 72.33,16.78 ; 16.95,8.57 J10.20 ; J10.20 17.75,7.12 ; J10.20 17.75,10.02 ; J10.20 18.55,8.57 ; 50.7,39.54 C68.2 ; C68.2 51.1,39.09 ; C68.2 51.1,39.69 50.82,39.97 ; 67.16,28.52 R65.1 ; R65.1 67.56,28.98 ; 58.26,36.55 C12.2 ; 43.55,18.85 J13.58 43.55,16.45 ; 43.11,46.69 CR2.2 42.79,46.34 ; R42.1 v1(66.49,30.98) ; 48.74,36.42 R45.2 ; R45.2 49.14,35.97 ; R45.2 49.14,36.88 ; 73.62,24.44 R104.2 ; R104.2 74.08,24.04 ; R104.2 74.53,24.44 ; 58.84,15.16 L14.6 ; J12.1 10.76,47.78 ; J12.1 v1(10,49.18) ; J12.1 9.24,47.78 ; 43.87,8.93 J7.B1 ; 50.48,37.73 U27.3 49.7,37.73 ; 38.75,16.45 J13.46 38.75,18.85 ; 50.64,35.16 C69.2 50.24,35.61 ; R58.2 52.19,26.99 ; 33.15,12.05 J13.31 33.15,14.45 ; v1(52.69,15.16) 52.72,15.16 L15.6 ; 7.36,18.73 C6.2 ; C6.2 8.27,18.73 ; C6.2 7.81,19.13 ; 52.33,33.81 C10.2 v1(51.6,34.45) ; L15.5 v1(54.51,15.16) ; 49.68,15.66 L21.C2 49.35,15.99 ; J10.11 24.75,10.62 ; 55.08,35.51 C22.2 56.24,35.51 ; 52.53,14.96 CR20.B1 52.21,14.64 ; J10.5 27.75,10.62 ; 49.3,12.38 J8.10 ; J8.10 50.2,13.82 ; J8.10 50.2,10.93 ; 50.27,40.55 C32.2 ; R56.1 59.5,37.96 ; L9.5 v1(47.13,10) ; 59.8,38.11 U5.3 60.58,38.11 ; 35.55,14.45 J13.37 35.55,12.05 ; J13.49 40.35,14.45 ; R64.1 58.43,34.87 ; J8.12 50.2,5.26 ; J8.12 50.2,2.5 ; J8.12 51.15,3.88 ; J8.12 49.25,3.88 ; v1(65.85,53.5) 65.38,53.5 ; R27.1 67.18,28.17 ; 75.72,14.89 75.73,14.87 v1(75.74,14.87) ; 28.02,25.68 C122.2 ; C97.2 47.38,21.63 ; C97.2 46.23,20.16 ; C97.2 48.53,20.16 ; C97.2 47.38,18.69 ; J12.2 v1(10,50.82) ; J12.2 9.24,52.22 ; J12.2 10,53.48 ; J12.2 10.76,52.22 ; L14.5 60.36,15.16 ; 71.39,33.09 71.29,33.09 70.98,33.4 ; 45.73,30.61 C60.2 45.15,31.16 ; v1(62.85,22.95) 63.08,22.95 63.08,22.91 63.16,22.99 C58.2 ; J7.M6 v1(40.35,11.63) ; 37,3.87 J7.M3 ; J7.M3 37.7,5.13 ; J7.M3 36.3,5.13 ; 47.45,32.82 C36.2 47.05,32.37 ; L4.5 73.67,15.16 v1(73.91,15.16) ; C2.2 66.34,34.76 ; 54.46,26.02 C61.2 ; 43.03,33.54 C35.2 43.03,32.21 v1(43.03,32.21) U22.5 43.03,31.16 ; 41.15,18.85 J13.52 41.15,16.45 ; 77.18,15.16 L3.6 ; L3.5 78.7,15.16 ; 25.15,18.85 J13.12 25.15,16.45 ; 54.06,30.48 C38.2 ; Y1.4 56.09,38.92 ; C132.2 72.27,16.07 ; 43.79,28.39 R62.2
  TOP w0.3: Y1.2 58.42,38.12 59.31,39.01 59.31,39.18 ; Y1.2 58.26,38.09 C12.2 58.71,37.01 v1(58.81,37.11) 58.81,37.6 Y1.2 ; J10.17 v1(21.75,8.17) ; Y1.4 56.99,39.72 ; Y1.4 55.19,39.72 ; Y1.4 56.09,40.52
  TOP w0.35: C131.2 v1(52.55,18.85) ; C31.2 v1(70.56,22.85) 70.47,22.76 C161.2
  TOP w0.4: J13.49 v1(40.35,11.63) ; Q5.4 74.05,37.06 ; Q5.4 74.05,35.95 ; Q5.4 74.47,36.51 ; C51.2 75.72,34.82 ; C51.2 74.76,34.11 ; C51.2 74.76,35.53 ; U14.4 TP59.1
  TOP w0.5: 9.9,32.22 15.19,32.22 ; 9.9,32.22 BT1.3 ; 9.9,32.22 13.76,36.08 ; 9.88,32.22 9.89,32.22 ; 9.88,32.22 6.14,35.96 ; 9.88,32.22 v1(4.44,32.22) ; 9.89,32.22 BT1.3 ; 9.89,32.22 6.04,28.37 ; 48,50.97 J12.40 ; J12.40 48.76,52.22 ; J12.40 48,53.48 ; BT1.3 9.89,32.22 ; BT1.3 9.64,32.47 9.64,37.66 ; 48,46.52 J12.39 ; J12.39 48.76,47.78 ; J12.39 48,49.03 ; J12.39 47.24,47.78 ; 13.77,28.34 9.89,32.22 ; 9.89,32.22 9.89,26.82 9.89,26.82 ; J4.2 74.9,46.09 ; J4.2 75.69,44.9 ; J4.2 74.9,43.71
  L2 w0.15: 37,7.18 J7.M1 ; J7.M1 37.7,8.33 ; J7.M1 37,9.48 ; J7.M1 36.3,8.33 ; 16.95,8.57 J10.20 ; J10.20 17.75,10.02 ; J10.20 17.75,7.12 ; J10.20 18.55,8.57 ; 50.2,2.5 J8.12 ; J8.12 50.2,5.26 ; J8.12 51.15,3.88 ; J8.12 49.25,3.88 ; 32.25,7.12 J10.23 ; J10.23 33.05,8.57 ; J10.23 32.25,10.02 ; J10.23 31.45,8.57 ; J8.4 60.1,12.37 ; J8.4 59.35,11.63 ; J8.4 60.1,10.88 ; J8.4 60.85,11.63 ; J7.M2 46.2,9.48 ; J7.M2 45.5,8.33 ; J7.M2 46.9,8.33 ; J7.M2 46.2,7.18 ; 78.75,11.63 J6.4 ; J6.4 80.25,11.63 ; J6.4 79.5,10.88 ; J6.4 79.5,12.37 ; J6.11 83.3,12.38 ; J6.11 82.4,10.93 ; J6.11 82.4,13.82 ; J6.11 81.5,12.38 ; 49.3,12.38 J8.10 ; J8.10 51.1,12.38 ; J8.10 50.2,13.82 ; J8.10 50.2,10.93 ; 36.3,5.13 J7.M3 ; J7.M3 37,6.39 ; J7.M3 37,3.87 ; J7.M3 37.7,5.13 ; J6.13 83.35,3.88 ; J6.13 82.4,2.5 ; J6.13 81.45,3.88 ; J6.13 82.4,5.26 ; 32.05,3.67 J10.22 ; J10.22 32.85,5.12 ; J10.22 32.85,2.22 ; J10.22 33.65,3.67 ; J8.7 56.6,13.87 ; J8.7 56.6,12.38 ; J8.7 55.85,13.13 ; J8.7 57.35,13.13 ; 76,12.38 J6.7 ; J6.7 75.25,13.13 ; J6.7 76,13.87 ; J6.7 76.75,13.13 ; 68.7,12.38 J6.10 ; J6.10 69.6,13.82 ; J6.10 70.5,12.38 ; J6.10 69.6,10.93 ; 62.05,3.88 J8.13 ; J8.13 63,5.26 ; J8.13 63.95,3.88 ; J8.13 63,2.5 ; 68.65,3.88 J6.12 ; J6.12 69.6,2.5 ; J6.12 70.55,3.88 ; J6.12 69.6,5.26 ; J10.21 17.15,5.12 ; J10.21 17.15,2.22 ; J10.21 16.35,3.67 ; J10.21 17.95,3.67 ; J7.B12 39.33,8.93 ; J8.11 63,13.82 ; J8.11 62.1,12.38 ; J8.11 63,10.93 ; J8.11 63.9,12.38 ; 46.2,3.87 J7.M4 ; J7.M4 46.2,6.39 ; J7.M4 46.9,5.13 ; J7.M4 45.5,5.13 ; 43.87,8.93 J7.B1
  L2 w0.5: J4.2 74.9,46.09 ; J4.2 75.69,44.9 ; J4.2 74.9,43.71
  L3 w0.15: J6.12 69.6,5.26 ; J6.12 68.65,3.88 ; J6.12 69.6,2.5 ; J6.12 70.55,3.88 ; J6.13 83.35,3.88 ; J6.13 81.45,3.88 ; J6.13 82.4,5.26 ; J6.13 82.4,2.5 ; J10.21 17.95,3.67 ; J10.21 17.15,2.22 ; J10.21 16.35,3.67 ; J10.21 17.15,5.12 ; J7.M1 37,9.48 ; J7.M1 37,7.18 ; J7.M1 36.3,8.33 ; J7.M1 37.7,8.33 ; J10.22 33.65,3.67 ; J10.22 32.85,2.22 ; J10.22 32.05,3.67 ; J6.7 76,13.87 ; J6.7 76,12.38 ; J6.7 76.75,13.13 ; J6.7 75.25,13.13 ; J8.7 57.35,13.13 ; J8.7 56.6,13.87 ; J8.7 56.6,12.38 ; J8.7 55.85,13.13 ; 62.1,12.38 J8.11 ; J8.11 63,10.93 ; J8.11 63.9,12.38 ; J8.11 63,13.82 ; J7.M4 46.9,5.13 ; J7.M4 46.2,6.39 ; J7.M4 45.5,5.13 ; J7.M4 46.2,3.87 ; J8.4 60.85,11.63 ; J8.4 60.1,10.88 ; J8.4 59.35,11.63 ; J8.4 60.1,12.37 ; 62.05,3.88 J8.13 ; J8.13 63,5.26 ; J8.13 63,2.5 ; J8.13 63.95,3.88 ; J7.B12 39.33,8.93 ; J6.4 80.25,11.63 ; J6.4 79.5,12.37 ; J6.4 78.75,11.63 ; J6.4 79.5,10.88 ; J10.20 18.55,8.57 ; J10.20 16.95,8.57 ; J10.20 17.75,10.02 ; J10.20 17.75,7.12 ; 49.3,12.38 J8.10 ; J8.10 51.1,12.38 ; J8.10 50.2,10.93 ; J8.10 50.2,13.82 ; 45.5,8.33 J7.M2 ; J7.M2 46.2,7.18 ; J7.M2 46.2,9.48 ; J7.M2 46.9,8.33 ; J10.23 33.05,8.57 ; J10.23 32.25,10.02 ; J10.23 31.45,8.57 ; J10.23 32.25,7.12 ; J6.11 83.3,12.38 ; J6.11 82.4,13.82 ; J6.11 81.5,12.38 ; J6.11 82.4,10.93 ; 69.6,10.93 J6.10 ; J6.10 68.7,12.38 ; J6.10 70.5,12.38 ; J6.10 69.6,13.82 ; 37,3.87 J7.M3 ; J7.M3 36.3,5.13 ; J7.M3 37.7,5.13 ; J7.M3 37,6.39 ; 43.87,8.93 J7.B1 ; J8.12 51.15,3.88 ; J8.12 49.25,3.88 ; J8.12 50.2,2.5 ; J8.12 50.2,5.26
  L3 w0.5: 74.9,43.71 J4.2 ; J4.2 74.11,44.9 ; J4.2 75.69,44.9 ; J4.2 74.9,46.09
  L4 w0.15: 63,10.93 J8.11 ; J8.11 63,13.82 ; J8.11 63.9,12.38 ; J8.11 62.1,12.38 ; 60.1,10.88 J8.4 ; J8.4 59.35,11.63 ; J8.4 60.1,12.37 ; J8.4 60.85,11.63 ; 55.85,13.13 J8.7 ; J8.7 56.6,12.38 ; J8.7 57.35,13.13 ; J8.7 56.6,13.87 ; J10.22 33.65,3.67 ; J10.22 32.85,5.12 ; J10.22 32.85,2.22 ; J10.22 32.05,3.67 ; J10.23 33.05,8.57 ; J10.23 31.45,8.57 ; J10.23 32.25,10.02 ; J10.23 32.25,7.12 ; J8.10 50.2,13.82 ; J8.10 50.2,10.93 ; J8.10 51.1,12.38 ; J8.10 49.3,12.38 ; 36.3,8.33 J7.M1 ; J7.M1 37.7,8.33 ; J7.M1 37,9.48 ; J7.M1 37,7.18 ; 46.2,7.18 J7.M2 ; J7.M2 46.9,8.33 ; J7.M2 45.5,8.33 ; J7.M2 46.2,9.48 ; J6.13 83.35,3.88 ; J6.13 82.4,2.5 ; J6.13 82.4,5.26 ; J6.13 81.45,3.88 ; J8.13 63.95,3.88 ; J8.13 63,5.26 ; J8.13 63,2.5 ; J8.13 62.05,3.88 ; J6.11 82.4,13.82 ; J6.11 83.3,12.38 ; J6.11 82.4,10.93 ; J6.11 81.5,12.38 ; J7.B12 39.33,8.93 ; 78.75,11.63 J6.4 ; J6.4 79.5,10.88 ; J6.4 80.25,11.63 ; J6.4 79.5,12.37 ; J10.21 17.95,3.67 ; J10.21 17.15,5.12 ; J10.21 17.15,2.22 ; J10.21 16.35,3.67 ; 69.6,10.93 J6.10 ; J6.10 68.7,12.38 ; J6.10 70.5,12.38 ; J6.10 69.6,13.82 ; 50.2,2.5 J8.12 ; J8.12 50.2,5.26 ; J8.12 49.25,3.88 ; J8.12 51.15,3.88 ; 43.87,8.93 J7.B1 ; J10.20 18.55,8.57 ; J10.20 17.75,10.02 ; J10.20 16.95,8.57 ; J10.20 17.75,7.12 ; J6.7 76.75,13.13 ; J6.7 76,12.38 ; J6.7 76,13.87 ; J6.7 75.25,13.13 ; J7.M4 46.9,5.13 ; J7.M4 45.5,5.13 ; J7.M4 46.2,3.87 ; J7.M4 46.2,6.39 ; 68.65,3.88 J6.12 ; J6.12 69.6,2.5 ; J6.12 69.6,5.26 ; J6.12 70.55,3.88 ; 36.3,5.13 J7.M3 ; J7.M3 37.7,5.13 ; J7.M3 37,6.39 ; J7.M3 37,3.87
  L4 w0.5: 74.11,44.9 J4.2 ; J4.2 74.9,43.71 ; J4.2 75.69,44.9 ; J4.2 74.9,46.09
  L5 w0.075: v4(8.85,17.43) 8.84,17.43 ; v4(8.85,17.43) 8.63,17.66 7.91,17.66 7.51,18.05 7.51,18.08 7.07,18.52 v1(7.05,18.52) ; v4(8.85,17.43) 9.08,17.66 9.61,17.66 v1(10.45,18.5)
  L5 w0.15: 36.3,8.33 J7.M1 ; J7.M1 37.7,8.33 ; J7.M1 37,7.18 ; J7.M1 37,9.48 ; J7.M4 46.9,5.13 ; J7.M4 46.2,6.39 ; J7.M4 46.2,3.87 ; J7.M4 45.5,5.13 ; J10.21 17.15,5.12 ; J10.21 17.15,2.22 ; J10.21 17.95,3.67 ; J10.21 16.35,3.67 ; 69.6,2.5 J6.12 ; J6.12 70.55,3.88 ; J6.12 69.6,5.26 ; J6.12 68.65,3.88 ; 32.05,3.67 J10.22 ; J10.22 32.85,2.22 ; J10.22 32.85,5.12 ; J10.22 33.65,3.67 ; 62.1,12.38 J8.11 ; J8.11 63.9,12.38 ; J8.11 63,10.93 ; J8.11 63,13.82 ; 75.25,13.13 J6.7 ; J6.7 76,13.87 ; J6.7 76,12.38 ; J6.7 76.75,13.13 ; J6.13 82.4,5.26 ; J6.13 83.35,3.88 ; J6.13 82.4,2.5 ; J6.13 81.45,3.88 ; 49.25,3.88 J8.12 ; J8.12 50.2,5.26 ; J8.12 50.2,2.5 ; J8.12 51.15,3.88 ; J8.4 60.1,12.37 ; J8.4 60.85,11.63 ; J8.4 60.1,10.88 ; J8.4 59.35,11.63 ; 36.3,5.13 J7.M3 ; J7.M3 37.7,5.13 ; J7.M3 37,3.87 ; J7.M3 37,6.39 ; J10.20 18.55,8.57 ; J10.20 17.75,7.12 ; J10.20 17.75,10.02 ; J10.20 16.95,8.57 ; J8.10 51.1,12.38 ; J8.10 50.2,10.93 ; J8.10 50.2,13.82 ; J8.10 49.3,12.38 ; J8.13 63,5.26 ; J8.13 63,2.5 ; J8.13 62.05,3.88 ; J8.13 63.95,3.88 ; 81.5,12.38 J6.11 ; J6.11 82.4,13.82 ; J6.11 83.3,12.38 ; J6.11 82.4,10.93 ; J7.B12 39.33,8.93 ; J7.M2 46.9,8.33 ; J7.M2 46.2,7.18 ; J7.M2 46.2,9.48 ; J7.M2 45.5,8.33 ; J10.23 33.05,8.57 ; J10.23 32.25,10.02 ; J10.23 31.45,8.57 ; J10.23 32.25,7.12 ; J6.4 79.5,12.37 ; J6.4 78.75,11.63 ; J6.4 80.25,11.63 ; J6.4 79.5,10.88 ; 68.7,12.38 J6.10 ; J6.10 69.6,10.93 ; J6.10 70.5,12.38 ; J6.10 69.6,13.82 ; 55.85,13.13 J8.7 ; J8.7 56.6,12.38 ; J8.7 57.35,13.13 ; J8.7 56.6,13.87 ; 43.87,8.93 J7.B1
  L5 w0.5: J4.2 74.9,46.09 ; J4.2 74.9,43.71 ; J4.2 75.69,44.9 ; J4.2 74.11,44.9
  BOTTOM w0.2: 14.55,39.26 L18.10 L18.9 L19.10 L19.9 9.75,39.26 ; 50.2,2.5 J8.12 ; J8.12 49.25,3.88 ; J8.12 50.2,5.26 ; J8.12 51.15,3.88 ; 43.87,8.93 J7.B1 ; 18.8,25.21 C45.2 ; C45.2 19.96,25.21 ; C45.2 v1(19.38,24.51) C44.2 ; 60.1,10.88 J8.4 ; J8.4 59.35,11.63 ; J8.4 60.85,11.63 ; J8.4 60.1,12.37 ; 23.07,11.53 C5.2 ; 45.5,5.13 J7.M4 ; J7.M4 46.2,6.39 ; J7.M4 46.9,5.13 ; J7.M4 46.2,3.87 ; 16.35,3.67 J10.21 ; J10.21 17.95,3.67 ; J10.21 17.15,2.22 ; J10.21 17.15,5.12 ; v1(22.24,7.3) 22.23,7.29 22.23,7.28 C11.2 21.7,8.12 v1(21.75,8.17) 21.69,8.23 CR28.B2 ; 73.29,37.55 J20.4 ; J20.4 74.28,37.55 ; J20.4 73.79,36.56 ; 43.06,12.05 U4.C2 43.06,12.71 ; 68.65,3.88 J6.12 ; J6.12 69.6,2.5 ; J6.12 70.55,3.88 ; J6.12 69.6,5.26 ; 70.27,45.55 70.06,45.34 70.06,44.96 70.27,44.75 70.27,44.73 ; v1(25.38,41.5) J3.91 25.38,43.06 ; C63.2 44.96,15.09 ; C63.2 44.96,13.93 ; C63.2 45.51,14.51 ; v1(15.38,41.5) J3.41 15.38,43.01 ; J3.30 v1(12.98,44.24) ; v1(37.23,21.46) 37.23,22.46 v1(37.28,22.51) J2.73 37.28,24.03 ; J10.22 33.65,3.67 ; J10.22 32.85,5.12 ; J10.22 32.05,3.67 ; 58.84,46.81 R23.2 59.24,46.36 ; J2.100 42.48,26.84 ; J2.100 42.78,26.29 ; J2.100 v1(42.48,25.24) ; 26.8,9.71 L10.10 v4(26.36,9.71) v4(24.84,9.71) L10.9 24.4,9.71 ; 81.5,12.38 J6.11 ; J6.11 82.4,10.93 ; J6.11 83.3,12.38 ; J6.11 82.4,13.82 ; J17.5 3.25,15.79 ; J17.5 2.7,14.94 v1(2.7,15.94) ; J17.5 5.1,14.39 ; J17.5 3.25,12.99 ; J17.5 1.4,14.39 ; J17.3 8.25,11.37 v1(7.93,11.69) ; J17.3 10.1,10.89 ; J17.3 6.4,10.89 ; J17.3 8.25,10.24 ; J7.M1 37.7,8.33 ; J7.M1 37,7.18 ; J7.M1 36.3,8.33 ; J7.M1 37,9.48 ; 76,12.38 J6.7 ; J6.7 75.25,13.13 ; J6.7 76.75,13.13 ; J6.7 76,13.87 ; 22.26,11.53 C140.2 21.8,11.93 ; J17.4 3.25,5.79 ; J17.4 1.4,4.39 ; J17.4 5.1,4.39 ; J17.4 v1(3.25,2.84) ; 63.72,19.84 R80.2 63.32,20.3 ; 8.58,45.83 J3.8 v1(8.58,44.24) ; 72.36,36.53 J20.2 ; J20.2 73.28,36.53 ; J20.2 72.82,36.98 ; 14.75,39.26 L20.9 L20.10 17.15,39.26 ; J3.99 v1(26.98,43.24) ; J3.99 27.28,42.2 ; J3.99 v1(26.98,41.5) ; 45.23,15.71 C62.2 ; C62.2 45.63,16.17 ; C62.2 45.23,16.62 ; 11.78,43.03 J3.23 v1(11.78,41.5) ; CR28.B1 22.01,9.04 ; CR28.B1 21.69,9.36 ; CR28.B1 21.69,8.64 CR28.B2 ; v1(7.38,44.24) J3.2 7.38,45.58 7.17,45.79 7.17,46.16 7.35,46.34 ; 24.05,4.12 U26.5 v1(24.05,3.07) ; 64.72,19.9 64.72,20.36 ; 64.72,20.36 63.52,20.36 ; 64.72,20.36 64.72,20.83 ; 79.5,10.88 J6.4 ; J6.4 78.75,11.63 ; J6.4 80.25,11.63 ; J6.4 79.5,12.37 ; 31.45,8.57 J10.23 ; J10.23 32.25,7.12 ; J10.23 32.25,10.02 ; J8.10 51.1,12.38 ; J8.10 49.3,12.38 ; J8.10 50.2,13.82 ; J8.10 50.2,10.93 ; v1(33.5,10.65) 33.49,10.65 R14.2 32.95,10.2 ; v1(72.83,17.7) 72.83,17.71 72.83,18.17 72.71,18.29 R79.2 ; 17.78,45.83 J3.54 v1(17.78,44.24) ; 36.3,5.13 J7.M3 ; J7.M3 37.7,5.13 ; J7.M3 37,3.87 ; J7.M3 37,6.39 ; 38.53,21.58 C83.2 37.62,21.58 ; v1(8.28,12.04) 8.29,12.05 ; 75.73,42.43 R116.2 ; v1(32.08,25.24) J2.48 32.08,26.84 ; 30.66,20.32 C126.2 C129.2 29.54,20.72 29.25,21.01 ; 53.15,52.6 J22.1 ; J22.1 55.05,52.6 ; J22.1 54.1,53.35 ; J22.1 54.1,51.85 ; 57.68,44.74 58.08,44.74 ; CR32.2 11.54,52.57 ; CR32.2 11.54,51.87 ; CR32.2 v1(11.07,52.22) ; 5.63,14.54 C120.2 ; C120.2 5.63,15.46 ; C120.2 5.23,15 ; 63,2.5 J8.13 ; J8.13 63.95,3.88 ; J8.13 62.05,3.88 ; J8.13 63,5.26 ; v1(10.2,15.07) 10.23,15.04 C1.2 10.69,14.52 ; v1(14.18,44.24) J3.36 14.18,45.74 14.32,45.88 ; 60.24,46.55 U18.7 ; U18.7 60.24,47.48 ; U18.7 59.04,47.02 ; J21.2 75.24,29.84 ; J21.2 75.24,28.99 v1(75.51,28.72) ; J21.2 75.69,29.38 ; J21.2 74.78,29.38 ; J9.1 20.31,49.11 v1(20.24,49.18) ; J9.1 21.23,51.02 ; J9.1 22.07,49.11 ; 21.98,8.12 C15.2 ; C15.2 22.82,7.51 ; C15.2 23.66,8.12 ; C15.2 22.82,8.73 ; C7.2 31.93,19.46 ; C7.2 31.02,19.46 ; C7.2 31.47,19.06 ; 16.95,8.57 J10.20 ; J10.20 18.55,8.57 ; J10.20 17.75,10.02 ; v1(34.48,25.24) J2.60 34.48,26.84 ; 59.89,39.33 C99.2 59.31,38.78 ; 42.36,6.68 CR11.2 42.01,6.36 ; R143.2 26.07,5.63 ; J3.96 v1(26.18,44.24) ; J6.10 70.5,12.38 ; J6.10 69.6,13.82 ; J6.10 69.6,10.93 ; J6.10 68.7,12.38 ; v1(50.86,53.5) 50.82,53.54 C54.2 49.63,53.54 v1(49.59,53.5) ; v1(36.88,25.24) J2.72 36.88,26.84 ; 27.48,18.49 27.02,18.49 27.02,18.89 ; 76.19,37.49 C85.2 75.73,37.89 ; 9.36,11.74 C27.2 8.45,11.74 ; 72.68,17.48 C149.2 72.28,17.02 ; C82.2 22.68,4.91 ; C82.2 22.23,4.51 ; C82.2 v1(21.63,4.91) ; v1(15.38,44.24) J3.42 15.38,45.72 15.23,45.87 ; J20.3 72.35,37.55 ; J20.3 71.85,36.56 ; J20.3 71.36,37.55 ; J20.3 71.85,38.53 ; 25.78,43.05 J3.93 v1(25.78,41.2) ; 35.78,11.9 L6.6 ; 8.37,1.84 CR7.2 ; CR7.2 8.69,2.19 ; CR7.2 8.37,2.54 ; v1(30.75,14.92) 30.55,15.12 30.53,15.12 30.47,15.17 30.47,15.2 30.38,15.29 30.38,15.47 29.98,15.47 ; 81.45,3.88 J6.13 ; J6.13 82.4,5.26 ; J6.13 82.4,2.5 ; J6.13 83.35,3.88 ; 24.18,43.02 J3.85 v1(24.18,41.5) ; 62.56,16.95 R82.2 ; 20.58,24.35 C43.2 20,23.8 ; 59.24,50.06 J23.1 ; J23.1 59.24,51.56 ; J23.1 58.29,50.81 ; 75.43,20.25 75.43,20.71 75.03,20.71 ; v1(12.98,41.5) J3.29 12.98,43.02 ; 30.26,12.7 U3.14 29.64,12.7 ; 30.26,12.7 30.69,12.27 R20.2 R16.2 30.64,13.08 30.26,12.7 ; J2.96 v1(41.68,25.25) ; 63,10.93 J8.11 62.1,12.38 ; 20.58,24.66 C46.2 20,25.21 ; 24.11,20.57 C39.2 23.2,20.57 ; 8.98,45.83 J3.10 v1(8.98,43.94) ; 18.98,45.83 J3.60 v1(18.98,44.24) ; 29.91,9.56 C21.2 30.36,9.96 ; v1(10.45,18.5) 10.45,19.05 ; 30.73,26.87 30.88,26.72 J2.42 v1(30.88,25.24) ; v1(10.58,41.5) J3.17 10.58,43.01 ; 55.85,13.13 J8.7 ; J8.7 56.6,13.87 ; J8.7 56.6,12.38 ; J8.7 57.35,13.13 ; 76.19,17.24 R124.2 ; R124.2 76.64,17.64 ; R124.2 75.73,17.64 ; v1(14.18,41.5) J3.35 14.18,43.02 ; 6.59,39.38 C134.2 ; C134.2 7.75,39.38 ; C134.2 7.17,38.83 ; 75.03,21.52 75.43,21.52 75.43,21.98 ; 33.83,15.57 R18.2 ; C19.2 42.08,6.12 ; C19.2 42.08,5.21 ; C19.2 42.48,5.66 ; v1(44.95,13.41) 44.94,13.41 ; 8.18,43.01 J3.5 v1(8.18,41.5) ; L8.5 44.36,6.74 ; J21.4 74.77,28.36 ; J21.4 74.27,27.38 ; J21.4 74.27,29.35 ; 25.61,2.51 C159.2 ; C159.2 25.16,2.91 ; C159.2 26.07,2.91 ; 40.08,13.16 CR12.2 40.4,12.81 ; 45.5,8.33 J7.M2 ; J7.M2 46.2,7.18 ; J7.M2 46.9,8.33 ; 74.27,19.5 74.27,19.96 ; 74.27,19.96 74.67,19.96 ; 74.27,19.96 74.27,20.41 ; CR28.B2 22.01,8.64 ; 39.68,26.84 J2.86 39.68,25.29 39.64,25.25 v1(39.62,25.25) ; CR10.B2 44.7,13.2 ; J7.B12 39.33,8.93 ; J7.B12 39.18,9.31 v1(39.59,9.31) ; J7.B12 38.73,8.93 v1(38.13,8.33) ; 8.83,40.12 C118.2 8.83,41.03 ; 9.01,46.17 C125.2 ; J2.98 v1(42.08,24.94) ; C137.2 15.29,47.75 ; C137.2 14.74,48.33 ; C137.2 14.74,47.17 ; C44.2 19.96,23.8 ; C44.2 18.8,23.8 ; v1(20.58,41.5) J3.67 20.58,43.04 ; 75.03,39.36 75.43,39.36 75.43,39.81 ; J3.90 v1(24.98,44.24) ; 11.64,6.47 C106.2 ; C106.2 v1(12.24,6.87) ; C106.2 11.19,6.87 ; 28.8,17.73 28.52,17.73 28.52,18.05 ; v1(33.28,25.24) J2.54 33.28,26.84 ; J3.80 v1(22.98,44.24) ; 29.63,9.52 29.44,9.71 v4(29.23,9.71) v4(27.64,9.71) L11.9 27.2,9.71 ; v1(23.28,25.24) J2.4 v1(23.28,26.99) 23.06,27.21 23.06,27.96 23.05,27.96 23.05,28.06 C47.2 23.65,28.12 v1(23.66,28.13) 23.76,28.22 C48.2 24.21,28.02 24.55,27.67 24.55,27.06 v1(24.48,26.99) J2.10 v1(24.48,25.24) ; v1(35.68,25.24) J2.66 35.68,26.84 ; 76.21,27.38 J21.3 76.21,29.35 ; 42.84,6.74 L8.6 ; 30.13,16.28 C34.2 ; 26.48,24.04 J2.19 v1(26.48,22.51) ; J2.82 v1(38.88,25.24) ; J3.84 v1(23.78,44.24) ; 8.34,14.83 C28.2 ; J3.74 v1(21.78,44.24) ; 24.82,20.57 C40.2 v1(25.88,20.57) ; C20.2 40.09,15.66 ; C20.2 40.09,14.76 ; C20.2 39.69,15.21 ; 67.15,48.87 C95.2 67.61,48.47 ; 14.85,46.74 C121.2 14.45,46.28 ; 44.71,13.6 CR10.B1 44.39,13.92 ; J3.24 v1(11.78,44.24) ; v1(42.72,21.15) 42.72,21.7 ; 1.95,47.98 v1(1.95,47.98) ; L6.5 37.3,11.9 ; J3.48 v1(16.58,44.24) ; J3.16 v1(10.18,44.24) ; 24.12,2.46 v1(24.67,2.46) ; 31.59,11.01 31.59,11.46 ; 19.38,43.02 J3.61 v1(19.38,41.5)
  BOTTOM w0.25: J21.3 75.8,28.36 v1(75.52,28.08) ; R116.2 v1(76.19,42.98)
  BOTTOM w0.3: 58.08,43.93 58.08,44.74 ; 66.8,43.24 v1(66.71,43.14) 66.4,43.45 C88.2 66.8,43.71 ; 67.15,44.26 67.15,43.86
  BOTTOM w0.35: v1(62.01,17.05) 62.37,17.41 R82.2 ; v1(67.83,16.25) 67.78,16.3 C152.2 67.02,16.3 ; C153.2 v1(67.81,14.63) ; 68.55,26.35 68,26.35 v1(67.94,26.41) ; C151.2 62.42,18.22 v1(62.01,17.81) ; C100.2 v1(67.34,13.2)
  BOTTOM w0.4: C93.2 63.25,43.79 ; C93.2 62.64,42.95 ; C93.2 63.25,42.11 ; C93.2 63.86,42.95 ; 68.56,23.16 C146.2 C145.2 ; 47.63,53.15 CR26.2 49.23,53.15 ; C145.2 67.95,25.66 ; C145.2 68.56,24.82 ; 61.39,42.95 C91.2 ; C91.2 62,43.79 ; C91.2 62.61,42.95 ; 66.41,14.63 C153.2 ; C153.2 67.02,13.79 ; C153.2 67.07,14.68 C152.2 67.07,17.14 ; 66.64,13.78 C100.2 66.64,12.62 ; 62,40.45 C92.2 ; C92.2 61.39,41.29 ; C92.2 62.61,41.29 ; 67.54,48.96 C94.2 68.38,48.35
  BOTTOM w0.5: 36.19,49.86 CR19.2 ; CR19.2 37.69,51.66 ; CR19.2 39.19,49.86 ; CR19.2 37.69,48.06 ; 67.95,24.81 v1(67.19,24.81) ; 74.9,43.71 J4.2 ; J4.2 75.69,44.9 ; J4.2 74.11,44.9 ; J4.2 74.9,46.09 ; C146.2 v1(67.19,23.16) ; U18.7 61.38,47.02 61.39,47.01 ; C92.2 C91.2 ; 64.72,20.36 65.92,20.36
  BOTTOM w0.7: 64.53,26.93 CR25.2 ; CR25.2 67.53,26.93 ; CR25.2 66.03,28.73
  vias: v1(0.51,53.49) v1(0.51,52.51) v1(0.51,50.51) v1(0.51,48.51) v1(0.51,46.51) v1(0.51,44.51) v1(0.51,42.51) v1(0.51,40.51) v1(0.51,38.51) v1(0.51,36.51) v1(0.51,34.51) v1(0.51,32.51) v1(0.51,30.51) v1(0.51,28.51) v1(0.51,26.51) v1(0.51,24.51) v1(0.51,22.51) v1(0.51,20.51) v1(0.51,18.51) v1(0.51,16.51) v1(0.51,14.51) v1(0.51,12.51) v1(0.51,10.51) v1(0.5,9.46) v1(0.51,8.51) v1(0.5,5.27) v1(0.5,3.72) v1(0.51,0.51) v1(1.04,28.02) v1(1.01,3.78) v1(1.99,52.05) v1(1.99,20.55) v1(1.95,16.48) v1(2.32,26.92) v1(2.51,53.49) v1(2.59,0.51) v1(3.45,34.43) v1(3.48,31.98) v1(3.45,29.89) v1(3.82,21.73) v1(4.19,28.13) v1(4.29,36.25) v1(4.51,53.49) v1(4.51,0.51) v1(4.61,34.33) v1(4.58,30.54) v1(4.91,40.58) v1(4.92,21.48) v1(5.01,27.46) v1(5.12,29.12) v1(5.29,38.77) v1(5.29,15.59) v1(5.42,37.45) v1(5.43,26.78) v1(5.39,14.04) v1(5.53,46.28) v1(5.5,42.03) v1(5.47,39.52) v1(5.51,35.84) v1(5.5,22.2) v1(5.56,45.39) v1(5.63,23) v1(5.67,15.92) v1(5.69,2.44) v1(5.84,0.55) v1(5.98,47.92) v1(6.06,51.98) v1(6.06,20.48) v1(6.2,22.31) v1(6.34,23.27) v1(6.28,14.1) v1(6.51,53.49) v1(6.51,0.51) v1(6.69,20.54) v1(6.67,19.82) v1(6.76,38.64) v1(6.89,36.93) v1(7.06,14.02) v1(7.55,48.73) v1(7.68,46.57) v1(7.98,44.26) v1(7.98,38.26) v1(8.12,20.57) v1(8.28,21.97) v1(8.38,21.13) v1(8.44,2.75) v1(8.51,53.49) v1(8.51,0.51) v1(8.75,46) v1(8.83,46.51) v1(8.78,41.47) v1(8.76,38.27) v1(8.83,14.73) v1(8.87,52.22) v1(8.99,50.93) v1(9.01,48.62) v1(9.09,49.36) v1(9.41,22.9) v1(9.72,49.97) v1(9.93,22.91) v1(10.05,41.48) v1(10.06,2.99) v1(10.51,0.51) v1(10.95,53.49) v1(11.02,51.15) v1(11.46,2.05) v1(11.66,18.14) v1(11.83,14.87) v1(11.83,13.12) v1(11.84,2.88) v1(11.94,15.5) v1(11.94,5.98) v1(11.89,4.64) v1(11.96,17.73) v1(11.97,16.29) v1(11.97,11.44) v1(12.06,12.07) v1(12.25,37.15) v1(12.33,13.2) v1(12.51,0.51) v1(12.59,49.62) v1(12.62,8.69) v1(12.62,4.72) v1(12.61,2.75) v1(12.65,22.51) v1(12.72,19.63) v1(12.9,25.8) v1(13.01,53.49) v1(12.99,51.58) v1(12.99,50.94) v1(12.98,48.57) v1(13.16,14.42) v1(13.43,25.8) v1(13.36,11.47) v1(13.56,24.31) v1(13.66,49.78) v1(13.7,12.1) v1(13.83,10.98) v1(13.85,8.7) v1(13.89,43.25) v1(13.89,6.96) v1(13.93,4.76) v1(13.96,3.13) v1(14.43,40.02) v1(14.56,43.82) v1(14.55,19.97) v1(14.73,40.43) v1(14.84,39.74) v1(14.93,49.84) v1(14.94,48.56) v1(14.95,43.42) v1(15,53.49) v1(15,51.37) v1(15.05,19.82) v1(15.06,46.97) v1(15.34,12.81) v1(15.42,12.14) v1(15.43,8.74) v1(15.43,5.97) v1(15.41,0.51) v1(15.51,14.4) v1(15.52,1.75) v1(15.68,34.84) v1(15.68,33.35) v1(15.69,31.51) v1(15.68,30.17) v1(15.66,29.04) v1(15.67,27.95) v1(15.78,43.25) v1(15.99,50.26) v1(15.99,44.15) v1(16.11,37.17) v1(16.19,18.69) v1(16.35,43.55) v1(16.39,18.23) v1(16.37,17.73) v1(16.38,16.29) v1(16.47,15.57) v1(16.58,27.06) v1(16.64,8.85) v1(16.69,9.69) v1(16.84,33.62) v1(16.82,17.96) v1(16.79,15.96) v1(16.95,47.62) v1(16.87,35.56) v1(16.85,31.46) v1(16.85,29.35) v1(16.86,5.38) v1(16.99,53.48) v1(16.98,48.54) v1(17,39.74) v1(17.08,49.86) v1(17.11,38.72) v1(17.07,14.44) v1(17.28,38.21) v1(17.38,1.74) v1(17.49,39.25) v1(17.7,50.32) v1(17.78,38.68) v1(17.77,38.04) v1(17.81,10.35) v1(18.07,0.51) v1(18.32,3.91) v1(18.4,44.24) v1(18.39,14) v1(18.44,13.21) v1(18.68,27.02) v1(18.71,25.83) v1(18.72,23.22) v1(18.77,24.52) v1(18.87,49.85) v1(18.89,7.74) v1(19.01,53.49) v1(19.02,1.7) v1(19.15,9.13) v1(19.45,30.73) v1(19.48,7.17) v1(19.62,49.24) v1(19.55,44.25) v1(19.56,33.56) v1(19.7,46.34) v1(19.73,8.44) v1(19.86,31.31) v1(20.14,50.36) v1(20.39,6.14) v1(20.51,0.51) v1(20.57,1.72) v1(20.77,21.29) v1(20.91,43.33) v1(21.01,53.49) v1(20.97,35.09) v1(21.59,11.92) v1(21.71,43.25) v1(21.78,40.52) v1(22.36,44.08) v1(22.41,4.27) v1(22.51,0.51) v1(22.67,11.41) v1(22.8,19) v1(22.87,43.63) v1(22.9,4.67) v1(23.02,47.65) v1(23.15,37.78) v1(23.28,24.64) v1(23.31,16.3) v1(23.38,39.55) v1(23.68,24.29) v1(23.68,7.43) v1(23.75,43.24) v1(23.99,18.99) v1(24,15.58) v1(24.01,7.03) v1(24.25,43.24) v1(24.26,15.15) v1(24.51,0.51) v1(24.6,11.28) v1(24.77,10.81) v1(24.81,3.02) v1(25.01,53.49) v1(24.99,52.53) v1(25.15,19) v1(25.24,49.69) v1(25.44,40.34) v1(25.41,39.1) v1(25.37,6.93) v1(25.53,39.72) v1(25.61,2.36) v1(25.83,24.69) v1(25.94,25.21) v1(26.07,39.98) v1(26.14,38.44) v1(26.08,28.74) v1(26.18,43.24) v1(26.17,36.9) v1(26.22,24.29) v1(26.27,5.8) v1(26.29,4.35) v1(26.44,6.37) v1(26.51,0.51) v1(26.61,25.21) v1(26.68,24.69) v1(27.01,53.49) v1(26.98,44.24) v1(27.09,39.81) v1(27.06,24.3) v1(27.17,25.21) v1(27.39,24.75) v1(27.53,5.27) v1(27.55,19) v1(27.61,6.1) v1(27.74,28.39) v1(27.72,24.33) v1(27.87,25.2) v1(28.03,24.73) v1(27.99,3.05) v1(28.22,4.31) v1(28.51,0.51) v1(28.9,6.09) v1(29.64,46.27) v1(29.64,2.56) v1(29.67,11.31) v1(29.77,49.52) v1(29.8,30.12) v1(29.77,6.43) v1(29.87,43.49) v1(29.95,16.29) v1(29.89,4.38) v1(30.27,25.25) v1(30.34,20.2) v1(30.26,9.41) v1(30.33,6.98) v1(30.37,43.42) v1(30.54,44.11) v1(30.51,0.51) v1(30.68,10.86) v1(30.66,3.18) v1(30.84,20.17) v1(30.85,5.36) v1(31.01,53.49) v1(30.99,51.68) v1(30.97,43.78) v1(31.02,6.26) v1(31.08,43.09) v1(31.16,7.86) v1(31.55,37.19) v1(31.69,6.09) v1(31.78,4.25) v1(31.86,32.63) v1(32.02,15.1) v1(32.2,37.21) v1(32.16,16.3) v1(32.51,0.51) v1(32.8,37.28) v1(32.8,6.11) v1(32.94,53.49) v1(33.14,21.26) v1(33.31,37.16) v1(33.75,29.7) v1(33.75,49.83) v1(33.79,11.05) v1(34,46.38) v1(33.97,4.18) v1(34.1,29.35) v1(34.41,9.37) v1(34.39,8.09) v1(34.42,2.56) v1(34.45,28.99) v1(34.51,0.51) v1(34.9,50.04) v1(34.85,37.11) v1(34.86,10) v1(35.01,53.49) v1(35.05,8.34) v1(35.09,41.68) v1(35.34,30.02) v1(35.55,14.6) v1(35.63,11.24) v1(35.8,31.98) v1(35.81,27.61) v1(35.95,4.58) v1(36.12,6.1) v1(36.15,10.11) v1(36.26,46.29) v1(36.29,25.24) v1(36.43,35.75) v1(36.35,19) v1(36.51,0.51) v1(36.66,30.12) v1(36.88,28.36) v1(37.01,53.49) v1(37.09,37.17) v1(37.17,19) v1(37.29,43.7) v1(37.39,31.98) v1(37.38,25.24) v1(37.72,19.01) v1(37.82,42.35) v1(37.9,7.44) v1(37.95,11.9) v1(38.22,19.04) v1(38.16,5.49) v1(38.35,46.31) v1(38.51,0.51) v1(38.6,44.15) v1(38.75,16.14) v1(38.9,4.03) v1(39.01,53.49) v1(39,7.44) v1(39.01,5.47) v1(39.34,49.86) v1(39.41,37) v1(39.53,50.8) v1(39.47,49.31) v1(39.5,46.29) v1(39.5,44.23) v1(39.73,40.1) v1(39.72,27.47) v1(39.82,5.58) v1(39.89,50.45) v1(39.89,49.84) v1(39.85,26.98) v1(39.96,49.23) v1(39.95,6.63) v1(40.15,14.61) v1(40.33,50.76) v1(40.33,50.17) v1(40.34,3.92) v1(40.36,49.57) v1(40.41,45.9) v1(40.41,44.99) v1(40.41,43.35) v1(40.51,0.51) v1(40.64,39.45) v1(40.93,40.43) v1(41.01,53.49) v1(41,51.48) v1(41.09,37.51) v1(41.06,36.57) v1(41.14,31.42) v1(41.15,19) v1(41.19,25.18) v1(41.21,3.98) v1(41.62,8.19) v1(41.68,50.7) v1(41.74,49.96) v1(41.68,49.27) v1(41.88,31.22) v1(41.88,30.72) v1(41.88,30.22) v1(42.15,43.56) v1(42.08,40.35) v1(42.25,50.41) v1(42.32,42.78) v1(42.32,41.68) v1(42.4,49.23) v1(42.4,2.45) v1(42.45,49.8) v1(42.5,6.26) v1(42.51,0.51) v1(42.63,50.83) v1(42.64,46.34) v1(42.65,43.4) v1(42.59,4.63) v1(42.69,7.24) v1(42.68,6.74) v1(42.74,5.75) v1(42.83,50.27) v1(42.83,41.62) v1(42.8,14.6) v1(42.85,11.63) v1(43.04,48.87) v1(43,47.98) v1(42.99,46.99) v1(42.95,19) v1(43.02,15.81) v1(43.09,43.63) v1(43.06,24.08) v1(43.2,50.7) v1(43.16,49.55) v1(43.3,33.69) v1(43.6,8.91) v1(43.84,28.25) v1(43.86,3.98) v1(44.09,2.45) v1(44.17,33.59) v1(44.18,31.11) v1(44.18,30.61) v1(44.19,29.67) v1(44.51,6.75) v1(44.51,0.51) v1(44.71,5.53) v1(44.78,8.29) v1(44.9,46.38) v1(44.94,45.6) v1(45.05,45.11) v1(44.95,26.61) v1(44.98,10.63) v1(45.06,44.61) v1(45.09,33.13) v1(45.08,32.61) v1(45.15,31.31) v1(45.16,31.85) v1(45.23,16.87) v1(45.3,28.12) v1(45.36,26.89) v1(45.42,22.57) v1(45.73,15.4) v1(45.71,14.52) v1(45.81,28.15) v1(45.82,20.66) v1(45.77,12.2) v1(45.79,2.45) v1(45.9,30.78) v1(45.9,30.2) v1(45.98,21.21) v1(46.15,22.28) v1(46.06,20.19) v1(46.33,10.45) v1(46.51,0.51) v1(46.86,11.9) v1(47.05,32.21) v1(47.17,53.5) v1(47.32,8.69) v1(47.36,46.34) v1(47.39,21.78) v1(47.37,18.52) v1(47.53,7.14) v1(47.53,5.57) v1(47.6,32.82) v1(47.58,3.06) v1(47.68,45.46) v1(47.65,28.2) v1(47.66,27.2) v1(47.83,15.97) v1(47.89,49.4) v1(47.94,37.25) v1(48.13,1.88) v1(48.24,32.62) v1(48.2,30.99) v1(48.2,30.44) v1(48.2,29.94) v1(48.2,29.38) v1(48.18,26.79) v1(48.15,13.52) v1(48.51,0.51) v1(48.59,36.42) v1(48.67,36.92) v1(48.72,32.78) v1(48.85,37.39) v1(48.9,12.57) v1(48.87,10.56) v1(48.93,8.75) v1(48.87,6.83) v1(49.14,31.8) v1(49.21,37.73) v1(49.17,15.93) v1(49.42,5.17) v1(49.53,38.19) v1(49.59,35.31) v1(49.87,30.92) v1(50.01,35.61) v1(50.12,40.55) v1(50.12,18.15) v1(50.3,9.77) v1(50.45,39.54) v1(50.51,0.51) v1(50.58,30.87) v1(50.62,15.37) v1(50.83,17.28) v1(50.9,33.71) v1(51.24,34.08) v1(51.37,11.48) v1(51.63,33.77) v1(51.83,53.48) v1(52.13,14.01) v1(52.33,53.49) v1(52.4,28.31) v1(52.52,19.38) v1(52.51,0.51) v1(52.71,26.58) v1(52.73,25.82) v1(52.74,25.03) v1(52.71,24.24) v1(52.69,23.49) v1(52.72,9.73) v1(52.83,53.5) v1(52.77,19.85) v1(52.85,17.68) v1(52.88,30.4) v1(52.9,29.72) v1(52.97,32.49) v1(53.43,38.73) v1(53.63,12.56) v1(53.73,53.5) v1(53.91,30.48) v1(53.91,28.98) v1(53.98,38.9) v1(54.04,23.86) v1(53.98,20.48) v1(54.05,11.16) v1(54.06,25.55) v1(54.2,18.91) v1(54.26,18.03) v1(54.36,19.73) v1(54.36,15.65) v1(54.47,38.71) v1(54.46,25.88) v1(54.51,0.51) v1(54.74,12.14) v1(54.83,18.49) v1(54.76,9.77) v1(54.93,35.2) v1(55.04,14.02) v1(55.15,53.49) v1(55.09,38.9) v1(55.21,36.69) v1(55.31,24.08) v1(55.25,23.12) v1(55.69,36.52) v1(56.18,20.46) v1(56.24,19.45) v1(56.25,18.47) v1(56.41,35.58) v1(56.45,27.15) v1(56.47,32.09) v1(56.45,28.23) v1(56.46,25.75) v1(56.55,11.12) v1(56.51,0.51) v1(56.77,30.98) v1(56.84,18.89) v1(56.8,15.9) v1(56.91,35.52) v1(56.85,28.53) v1(56.9,9.79) v1(57.11,19.38) v1(57.12,13.92) v1(57.33,18.46) v1(57.53,53.5) v1(57.49,44.75) v1(57.5,12.62) v1(57.59,13.22) v1(57.7,50.08) v1(57.82,13.92) v1(57.86,20.61) v1(58.29,18.43) v1(58.45,35.02) v1(58.51,0.51) v1(58.69,36.5) v1(58.68,15.12) v1(58.8,12.14) v1(58.83,11.15) v1(58.8,9.75) v1(58.85,32.08) v1(59.1,23.12) v1(59.08,19.41) v1(59.23,53.5) v1(59.39,46.36) v1(59.35,32.08) v1(59.5,38.11) v1(59.57,12.58) v1(59.66,38.61) v1(59.66,20.63) v1(59.89,46.36) v1(60.07,18.46) v1(60.26,14.06) v1(60.39,46.36) v1(60.42,19.87) v1(60.46,32.48) v1(60.51,15.16) v1(60.51,0.51) v1(60.7,37.21) v1(60.67,9.79) v1(60.8,32.08) v1(60.81,23.3) v1(60.93,53.5) v1(60.89,46.37) v1(60.94,40.01) v1(61.01,39.51) v1(61.14,12.27) v1(61.24,41.66) v1(61.39,47.71) v1(61.39,46.38) v1(61.47,18.82) v1(61.56,48.69) v1(61.58,34.47) v1(61.62,25.38) v1(61.59,20.56) v1(61.72,44.5) v1(61.74,3.65) v1(61.75,53.47) v1(61.81,48.26) v1(61.94,20.1) v1(61.92,10.71) v1(62.06,48.69) v1(62.12,25.38) v1(62.22,44.5) v1(62.31,48.26) v1(62.41,14.1) v1(62.51,53.49) v1(62.49,23.3) v1(62.51,0.51) v1(62.56,48.69) v1(62.62,25.38) v1(62.72,44.5) v1(62.81,48.26) v1(62.88,51.42) v1(62.97,6.39) v1(63.06,48.69) v1(63.12,25.37) v1(63.25,53.5) v1(63.22,44.5) v1(63.25,52.82) v1(63.31,48.26) v1(63.3,5.44) v1(63.37,20.45) v1(63.55,29.68) v1(63.55,29.08) v1(63.55,27.87) v1(63.55,27.27) v1(63.56,30.3) v1(63.55,28.47) v1(63.72,44.51) v1(63.69,2.45) v1(63.75,1.37) v1(63.77,0.6) v1(63.91,44.04) v1(63.95,29.99) v1(63.87,19.75) v1(64.01,41.29) v1(64,40.68) v1(63.95,29.38) v1(63.96,28.76) v1(63.95,28.17) v1(63.95,27.57) v1(64.22,44.5) v1(64.39,43.92) v1(64.52,49.47) v1(64.49,47.61) v1(64.78,5.64) v1(64.82,4.37) v1(66.2,14.25) v1(66.25,11.7) v1(66.19,4.52) v1(66.28,12.39) v1(66.42,17.85) v1(66.37,10.08) v1(66.51,53.49) v1(66.49,34.77) v1(66.49,34.1) v1(66.55,49.47) v1(66.55,21.61) v1(66.64,9.19) v1(66.68,17.41) v1(66.74,10.5) v1(66.8,9.74) v1(66.92,17.86) v1(67.05,49.46) v1(67.06,21.61) v1(67.18,17.41) v1(67.32,49.02) v1(67.34,11.68) v1(67.26,5.64) v1(67.36,53.5) v1(67.42,17.86) v1(67.36,7.42) v1(67.63,13.64) v1(67.59,5.19) v1(67.71,29.03) v1(67.68,28.18) v1(67.68,21.61) v1(67.68,17.4) v1(67.92,17.86) v1(68,14.07) v1(68.18,21.61) v1(68.18,17.4) v1(68.42,17.85) v1(68.37,12.23) v1(68.51,53.49) v1(68.68,17.4) v1(68.71,6.89) v1(68.7,5.95) v1(68.77,5.21) v1(68.85,2.08) v1(68.93,9.92) v1(69.11,53.5) v1(69.07,8.14) v1(69.29,1.78) v1(69.29,0.53) v1(69.41,15.12) v1(69.82,14.19) v1(69.97,53.49) v1(70,10.6) v1(70.51,0.51) v1(70.63,53.5) v1(70.74,11.4) v1(71,3.9) v1(70.99,1.55) v1(71.21,38.14) v1(71.21,37.63) v1(71.21,37.13) v1(71.34,40.05) v1(71.31,39.14) v1(71.37,24.61) v1(71.53,39.59) v1(71.54,38.7) v1(71.62,53.5) v1(71.64,8.1) v1(71.74,47.22) v1(72.51,53.49) v1(72.47,16.86) v1(73.06,12.6) v1(73.62,53.5) v1(73.8,15.75) v1(73.83,10.99) v1(74,17) v1(74.07,35.74) v1(74.21,23.84) v1(74.22,21.92) v1(74.15,21) v1(74.17,8.11) v1(74.33,33.41) v1(74.27,27.07) v1(74.43,23.24) v1(74.51,53.49) v1(74.61,47.51) v1(74.65,37.8) v1(74.69,51.1) v1(74.7,48.67) v1(74.69,46.36) v1(74.65,40.14) v1(74.66,37.17) v1(74.68,36.67) v1(74.68,36.17) v1(74.67,33.9) v1(74.79,43.43) v1(74.76,35.67) v1(74.83,33.43) v1(74.77,21.65) v1(74.94,40.55) v1(74.86,21.05) v1(75.01,30.05) v1(74.97,28.73) v1(74.97,28.07) v1(74.97,25.01) v1(75.1,51.57) v1(75.13,40) v1(75.16,37.84) v1(75.17,33.91) v1(75.2,22.69) v1(75.32,50.42) v1(75.35,49.47) v1(75.26,23.72) v1(75.33,17.64) v1(75.33,17.12) v1(75.37,48.67) v1(75.37,47.53) v1(75.42,40.69) v1(75.36,25.36) v1(75.49,46.12) v1(75.5,30.13) v1(75.51,24.59) v1(75.47,23.19) v1(75.53,22.18) v1(75.51,16.46) v1(75.59,37.58) v1(75.69,53.49) v1(75.68,33.9) v1(75.77,31.17) v1(75.92,45.23) v1(75.92,44.73) v1(75.94,29.9) v1(76.05,52.52) v1(75.95,35.04) v1(76.02,11.03) v1(76.1,33.32) v1(76.24,53.5) v1(76.17,51.63) v1(76.24,50.55) v1(76.19,46.2) v1(76.23,43.98) v1(76.15,37.21) v1(76.24,32.82) v1(76.17,32.32) v1(76.25,31.83) v1(76.25,31.32) v1(76.25,30.82) v1(76.25,29.5) v1(76.21,27.23) v1(76.19,17) v1(76.26,34.3) v1(76.26,33.8) v1(76.25,30.29) v1(76.82,36.87) v1(76.8,16.44) v1(77.03,15.16) v1(77.06,13.6) v1(77.07,12.64) v1(77.16,34.44) v1(77.21,17.07) v1(77.72,16.56) v1(78.1,11.49) v1(78.3,15.98) v1(78.85,15.16) v1(79.03,12.58) v1(79.1,36.87) v1(79.19,34.43) v1(79.22,6.92) v1(79.21,4.03) v1(79.23,0.52) v1(79.27,14.35) v1(79.91,14.37) v1(80.51,0.51) v1(80.62,12.21) v1(80.74,14.22) v1(81.12,13.01) v1(81.56,14.25) v1(81.9,36.88) v1(81.92,34.45) v1(82.51,0.51) v1(83.37,14.19) v1(84.43,36.82) v1(84.4,34.5) v1(84.49,14.25) v1(84.49,12.51) v1(84.49,10.51) v1(84.49,8.51) v1(84.49,6.51) v1(84.49,4.51) v1(84.49,2.51) v1(84.49,0.51)
